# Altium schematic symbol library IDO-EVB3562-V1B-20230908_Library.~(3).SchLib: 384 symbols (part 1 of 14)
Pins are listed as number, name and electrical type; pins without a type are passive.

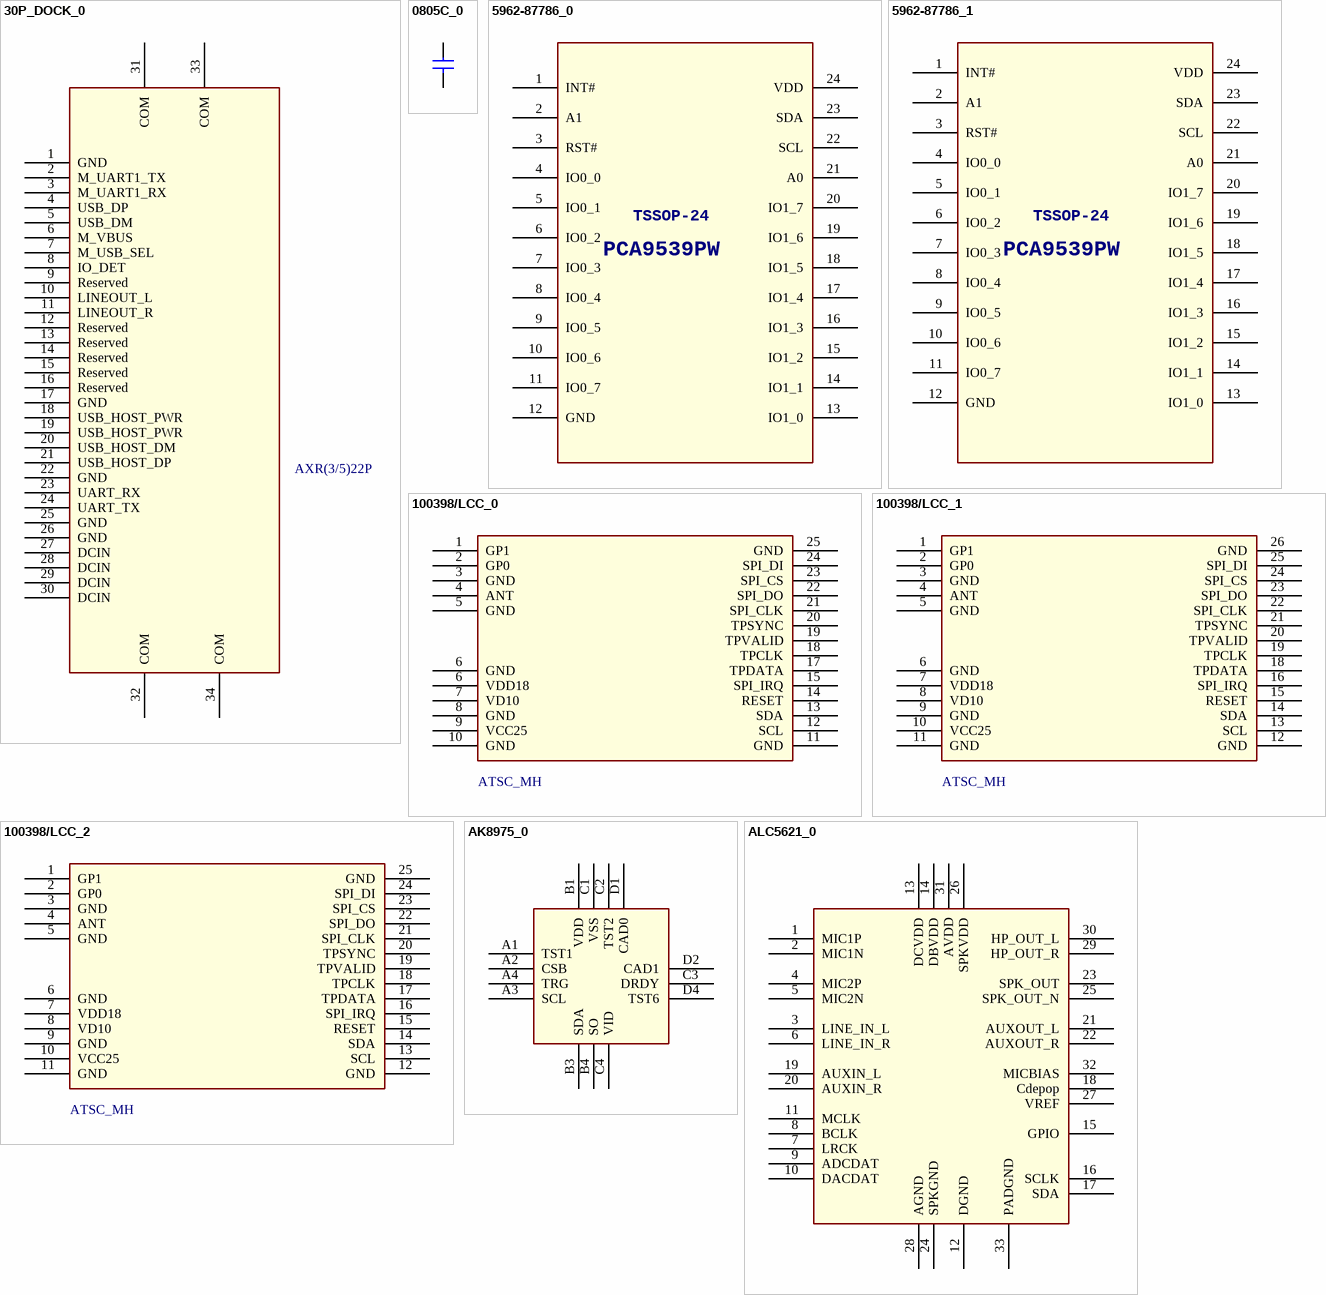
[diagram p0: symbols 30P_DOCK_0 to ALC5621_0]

## 30P_DOCK_0
designator CON?, comment AXR(3/5)22P
Altium-Right: 140; Altium-Bottom: 390
footprint 30P_DOCK_1
pins: 1 GND, 2 M_UART1_TX, 3 M_UART1_RX, 4 USB_DP, 5 USB_DM, 6 M_VBUS, 7 M_USB_SEL, 8 IO_DET, 9 Reserved, 10 LINEOUT_L, 11 LINEOUT_R, 12 Reserved, 13 Reserved, 14 Reserved, 15 Reserved, 16 Reserved, 17 GND, 18 USB_HOST_PWR, 19 USB_HOST_PWR, 20 USB_HOST_DM, 21 USB_HOST_DP, 22 GND, 23 UART_RX, 24 UART_TX, 25 GND, 26 GND, 27 DCIN, 28 DCIN, 29 DCIN, 30 DCIN, 31 COM, 32 COM, 33 COM, 34 COM

## 0805C_0
designator C?
Altium-Right: 20; Altium-Bottom: 10
footprint 0805C
pins: 1, 2

## 5962-87786_0
designator U?
Altium-Right: 170; Altium-Bottom: 280
pins: 1 INT#, 2 A1, 3 RST#, 4 IO0_0, 5 IO0_1, 6 IO0_2, 7 IO0_3, 8 IO0_4, 9 IO0_5, 10 IO0_6, 11 IO0_7, 12 GND, 13 IO1_0, 14 IO1_1, 15 IO1_2, 16 IO1_3, 17 IO1_4, 18 IO1_5, 19 IO1_6, 20 IO1_7, 21 A0, 22 SCL, 23 SDA, 24 VDD

## 5962-87786_1
designator U?
Altium-Right: 170; Altium-Bottom: 280
pins: 1 INT#, 2 A1, 3 RST#, 4 IO0_0, 5 IO0_1, 6 IO0_2, 7 IO0_3, 8 IO0_4, 9 IO0_5, 10 IO0_6, 11 IO0_7, 12 GND, 13 IO1_0, 14 IO1_1, 15 IO1_2, 16 IO1_3, 17 IO1_4, 18 IO1_5, 19 IO1_6, 20 IO1_7, 21 A0, 22 SCL, 23 SDA, 24 VDD

## 100398/LCC_0
designator U?, comment ATSC_MH
Altium-Right: 210; Altium-Bottom: 150
pins: 1 GP1, 2 GP0, 3 GND, 4 ANT, 5 GND, 6 VDD18, 6 GND, 7 VD10, 8 GND, 9 VCC25, 10 GND, 11 GND, 12 SCL, 13 SDA, 14 RESET, 15 SPI_IRQ, 17 TPDATA, 18 TPCLK, 19 TPVALID, 20 TPSYNC, 21 SPI_CLK, 22 SPI_DO, 23 SPI_CS, 24 SPI_DI, 25 GND

## 100398/LCC_1
designator U?, comment ATSC_MH
Altium-Right: 210; Altium-Bottom: 150
pins: 1 GP1, 2 GP0, 3 GND, 4 ANT, 5 GND, 6 GND, 7 VDD18, 8 VD10, 9 GND, 10 VCC25, 11 GND, 12 GND, 13 SCL, 14 SDA, 15 RESET, 16 SPI_IRQ, 18 TPDATA, 19 TPCLK, 20 TPVALID, 21 TPSYNC, 22 SPI_CLK, 23 SPI_DO, 24 SPI_CS, 25 SPI_DI, 26 GND

## 100398/LCC_2
designator U?, comment ATSC_MH
Altium-Right: 210; Altium-Bottom: 150
pins: 1 GP1, 2 GP0, 3 GND, 4 ANT, 5 GND, 6 GND, 7 VDD18, 8 VD10, 9 GND, 10 VCC25, 11 GND, 12 GND, 13 SCL, 14 SDA, 15 RESET, 16 SPI_IRQ, 17 TPDATA, 18 TPCLK, 19 TPVALID, 20 TPSYNC, 21 SPI_CLK, 22 SPI_DO, 23 SPI_CS, 24 SPI_DI, 25 GND

## AK8975_0
designator U?
Altium-Right: 90
footprint QFN16-4X4
pins: A1 TST1, A2 CSB, A3 SCL, A4 TRG, B1 VDD, B3 SDA, B4 SO, C1 VSS, C2 TST2, C3 DRDY, C4 VID, D1 CAD0, D2 CAD1, D4 TST6

## ALC5621_0
designator U?
Altium-Right: 170; Altium-Bottom: 210
footprint QFN32
pins: 1 MIC1P, 2 MIC1N, 3 LINE_IN_L, 4 MIC2P, 5 MIC2N, 6 LINE_IN_R, 7 LRCK, 8 BCLK, 9 ADCDAT, 10 DACDAT, 11 MCLK, 12 DGND, 13 DCVDD, 14 DBVDD, 15 GPIO, 16 SCLK, 17 SDA, 18 Cdepop, 19 AUXIN_L, 20 AUXIN_R, 21 AUXOUT_L, 22 AUXOUT_R, 23 SPK_OUT, 24 SPKGND, 25 SPK_OUT_N, 26 SPKVDD, 27 VREF, 28 AGND, 29 HP_OUT_R, 30 HP_OUT_L, 31 AVDD, 32 MICBIAS, 33 PADGND

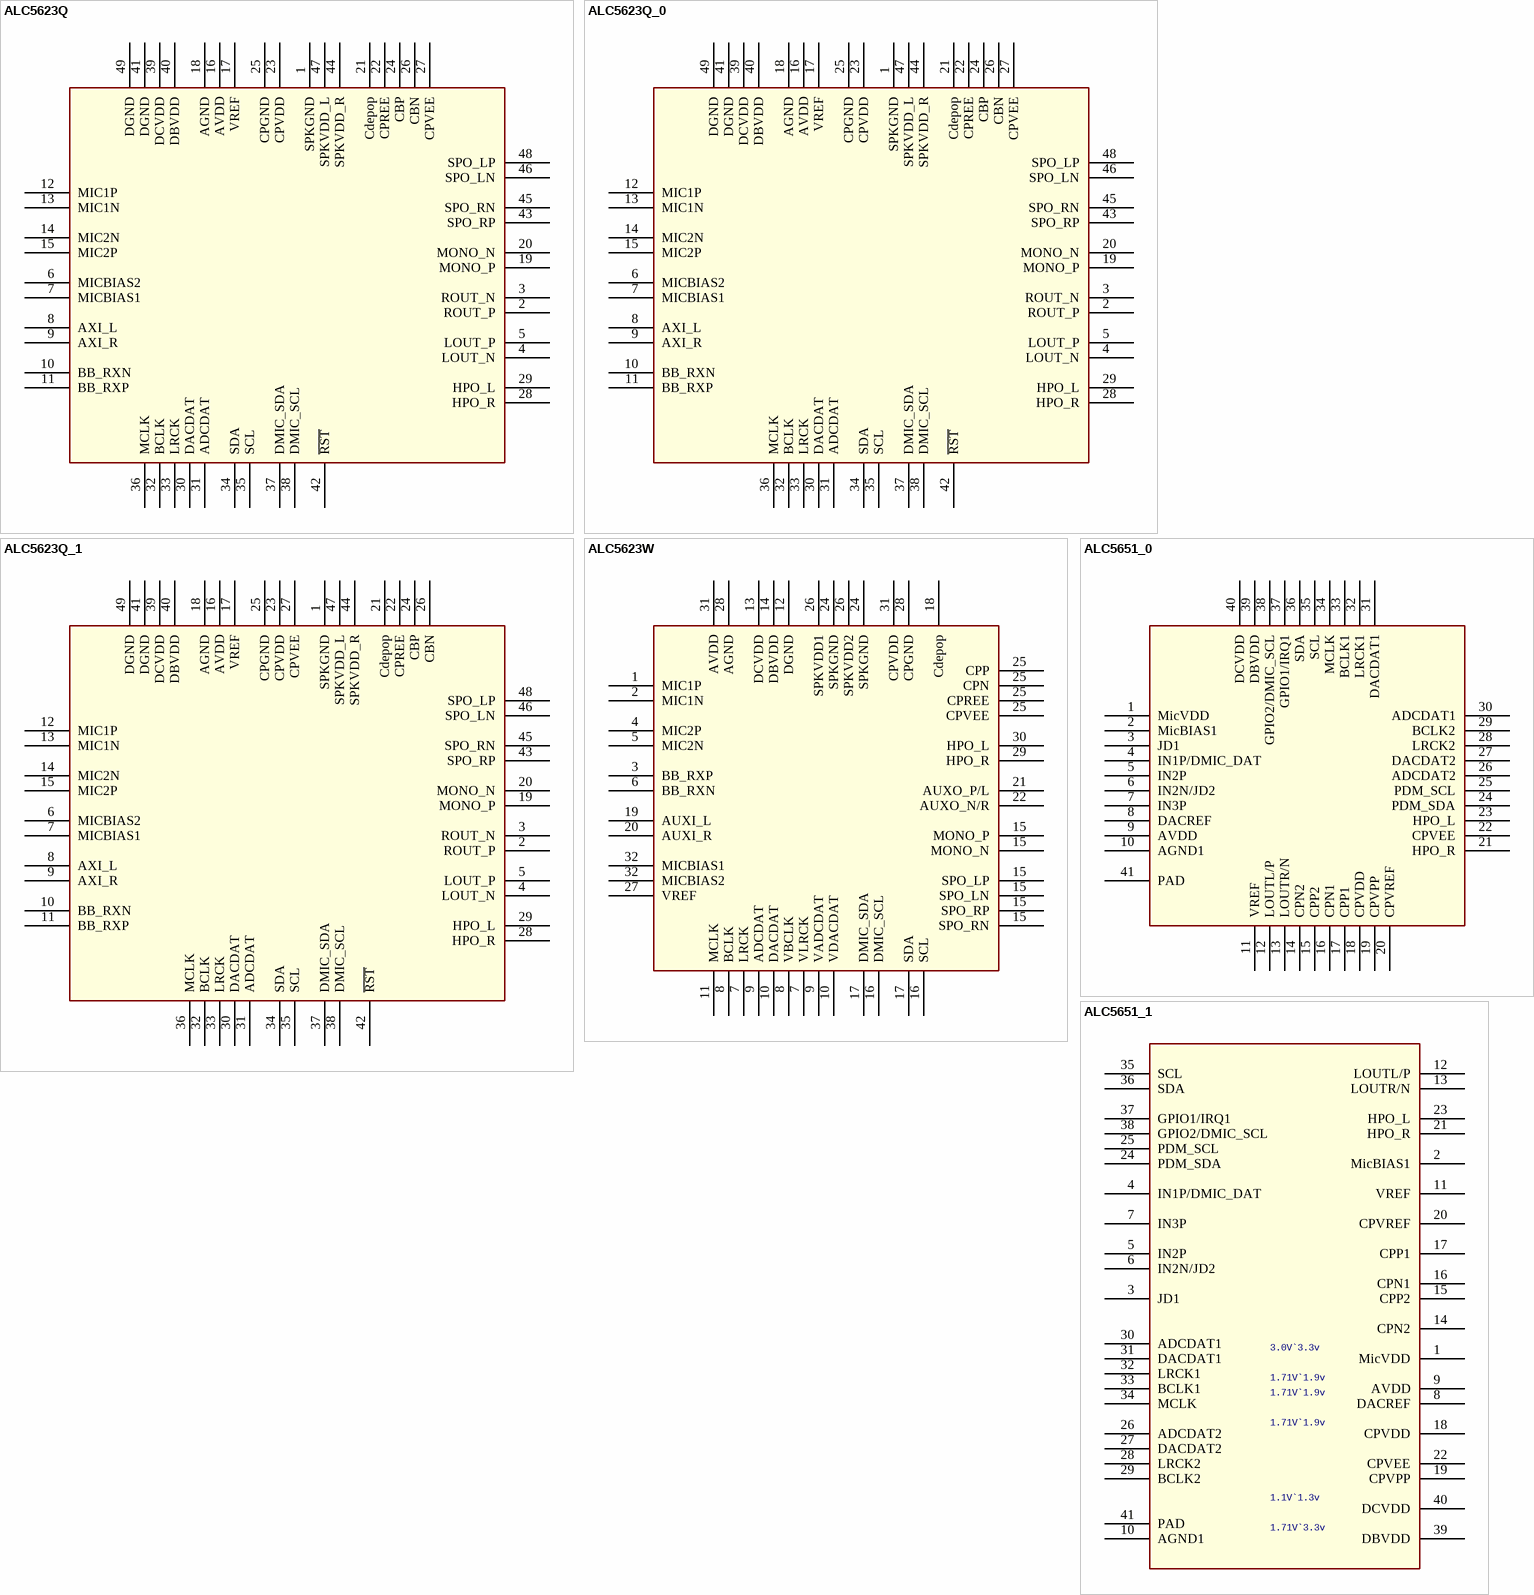
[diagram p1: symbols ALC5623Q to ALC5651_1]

## ALC5623Q
designator U?
Altium-Right: 290; Altium-Bottom: 250
footprint QFN48-6X6
pins: 1 SPKGND, 2 ROUT_P, 3 ROUT_N, 4 LOUT_N, 5 LOUT_P, 6 MICBIAS2, 7 MICBIAS1, 8 AXI_L, 9 AXI_R, 10 BB_RXN, 11 BB_RXP, 12 MIC1P, 13 MIC1N, 14 MIC2N, 15 MIC2P, 16 AVDD, 17 VREF, 18 AGND, 19 MONO_P, 20 MONO_N, 21 Cdepop, 22 CPREE, 23 CPVDD, 24 CBP, 25 CPGND, 26 CBN, 27 CPVEE, 28 HPO_R, 29 HPO_L, 30 DACDAT, 31 ADCDAT, 32 BCLK, 33 LRCK, 34 SDA, 35 SCL, 36 MCLK, 37 DMIC_SDA, 38 DMIC_SCL, 39 DCVDD, 40 DBVDD, 41 DGND, 42 ~{RST}, 43 SPO_RP, 44 SPKVDD_R, 45 SPO_RN, 46 SPO_LN, 47 SPKVDD_L, 48 SPO_LP, 49 DGND

## ALC5623Q_0
designator U?
Altium-Right: 290; Altium-Bottom: 250
footprint QFN48-6X6
pins: 1 SPKGND, 2 ROUT_P, 3 ROUT_N, 4 LOUT_N, 5 LOUT_P, 6 MICBIAS2, 7 MICBIAS1, 8 AXI_L, 9 AXI_R, 10 BB_RXN, 11 BB_RXP, 12 MIC1P, 13 MIC1N, 14 MIC2N, 15 MIC2P, 16 AVDD, 17 VREF, 18 AGND, 19 MONO_P, 20 MONO_N, 21 Cdepop, 22 CPREE, 23 CPVDD, 24 CBP, 25 CPGND, 26 CBN, 27 CPVEE, 28 HPO_R, 29 HPO_L, 30 DACDAT, 31 ADCDAT, 32 BCLK, 33 LRCK, 34 SDA, 35 SCL, 36 MCLK, 37 DMIC_SDA, 38 DMIC_SCL, 39 DCVDD, 40 DBVDD, 41 DGND, 42 ~{RST}, 43 SPO_RP, 44 SPKVDD_R, 45 SPO_RN, 46 SPO_LN, 47 SPKVDD_L, 48 SPO_LP, 49 DGND

## ALC5623Q_1
designator U?
Altium-Right: 290; Altium-Bottom: 250
footprint QFN48-6X6
pins: 1 SPKGND, 2 ROUT_P, 3 ROUT_N, 4 LOUT_N, 5 LOUT_P, 6 MICBIAS2, 7 MICBIAS1, 8 AXI_L, 9 AXI_R, 10 BB_RXN, 11 BB_RXP, 12 MIC1P, 13 MIC1N, 14 MIC2N, 15 MIC2P, 16 AVDD, 17 VREF, 18 AGND, 19 MONO_P, 20 MONO_N, 21 Cdepop, 22 CPREE, 23 CPVDD, 24 CBP, 25 CPGND, 26 CBN, 27 CPVEE, 28 HPO_R, 29 HPO_L, 30 DACDAT, 31 ADCDAT, 32 BCLK, 33 LRCK, 34 SDA, 35 SCL, 36 MCLK, 37 DMIC_SDA, 38 DMIC_SCL, 39 DCVDD, 40 DBVDD, 41 DGND, 42 ~{RST}, 43 SPO_RP, 44 SPKVDD_R, 45 SPO_RN, 46 SPO_LN, 47 SPKVDD_L, 48 SPO_LP, 49 DGND

## ALC5623W
designator U?
Altium-Right: 230
footprint GBA49
pins: 1 MIC1P, 2 MIC1N, 3 BB_RXP, 4 MIC2P, 5 MIC2N, 6 BB_RXN, 7 LRCK, 7 VLRCK, 8 BCLK, 8 VBCLK, 9 ADCDAT, 9 VADCDAT, 10 DACDAT, 10 VDACDAT, 11 MCLK, 12 DGND, 13 DCVDD, 14 DBVDD, 15 SPO_RN, 15 SPO_RP, 15 SPO_LP, 15 SPO_LN, 15 MONO_P, 15 MONO_N, 16 SCL, 16 DMIC_SCL, 17 SDA, 17 DMIC_SDA, 18 Cdepop, 19 AUXI_L, 20 AUXI_R, 21 AUXO_P/L, 22 AUXO_N/R, 24 SPKGND, 24 SPKGND, 25 CPVEE, 25 CPREE, 25 CPN, 25 CPP, 26 SPKVDD1, 26 SPKVDD2, 27 VREF, 28 AGND, 28 CPGND, 29 HPO_R, 30 HPO_L, 31 AVDD, 31 CPVDD, 32 MICBIAS1, 32 MICBIAS2

## ALC5651_0
designator U?
Altium-Right: 210; Altium-Bottom: 200
footprint QFN-5RX5RX1R
pins: 1 MicVDD, 2 MicBIAS1, 3 JD1, 4 IN1P/DMIC_DAT, 5 IN2P, 6 IN2N/JD2, 7 IN3P, 8 DACREF, 9 AVDD, 10 AGND1, 11 VREF, 12 LOUTL/P, 13 LOUTR/N, 14 CPN2, 15 CPP2, 16 CPN1, 17 CPP1, 18 CPVDD, 19 CPVPP, 20 CPVREF, 21 HPO_R, 22 CPVEE, 23 HPO_L, 24 PDM_SDA, 25 PDM_SCL, 26 ADCDAT2, 27 DACDAT2, 28 LRCK2, 29 BCLK2, 30 ADCDAT1, 31 DACDAT1, 32 LRCK1, 33 BCLK1, 34 MCLK, 35 SCL, 36 SDA, 37 GPIO1/IRQ1, 38 GPIO2/DMIC_SCL, 39 DBVDD, 40 DCVDD, 41 PAD

## ALC5651_1
designator U?
Altium-Right: 180; Altium-Bottom: 350
footprint QFN-5RX5RX1R
pins: 1 MicVDD, 2 MicBIAS1, 3 JD1, 4 IN1P/DMIC_DAT, 5 IN2P, 6 IN2N/JD2, 7 IN3P, 8 DACREF, 9 AVDD, 10 AGND1, 11 VREF, 12 LOUTL/P, 13 LOUTR/N, 14 CPN2, 15 CPP2, 16 CPN1, 17 CPP1, 18 CPVDD, 19 CPVPP, 20 CPVREF, 21 HPO_R, 22 CPVEE, 23 HPO_L, 24 PDM_SDA, 25 PDM_SCL, 26 ADCDAT2, 27 DACDAT2, 28 LRCK2, 29 BCLK2, 30 ADCDAT1, 31 DACDAT1, 32 LRCK1, 33 BCLK1, 34 MCLK, 35 SCL, 36 SDA, 37 GPIO1/IRQ1, 38 GPIO2/DMIC_SCL, 39 DBVDD, 40 DCVDD, 41 PAD

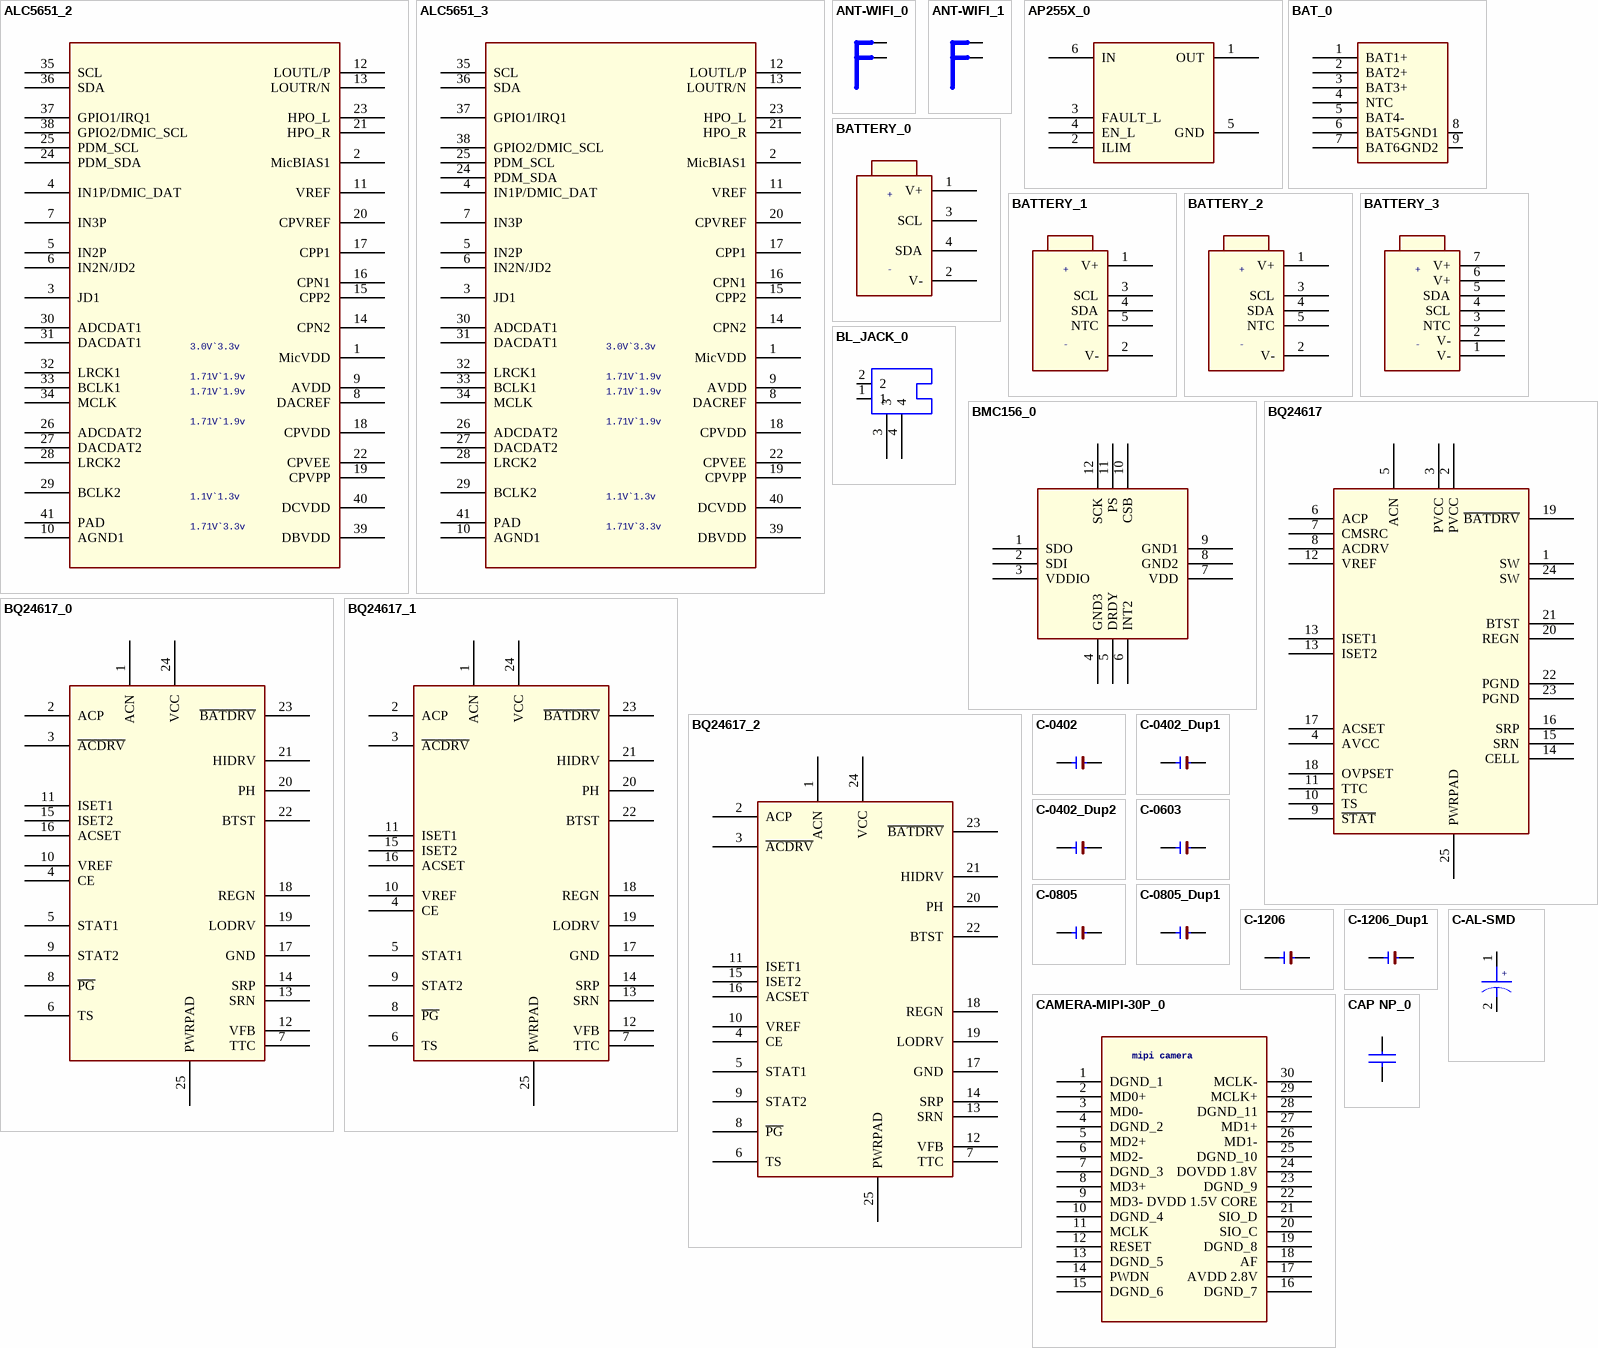
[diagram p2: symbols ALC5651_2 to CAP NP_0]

## ALC5651_2
designator U?
Altium-Right: 180; Altium-Bottom: 350
footprint QFN-5RX5RX1R
pins: 1 MicVDD, 2 MicBIAS1, 3 JD1, 4 IN1P/DMIC_DAT, 5 IN2P, 6 IN2N/JD2, 7 IN3P, 8 DACREF, 9 AVDD, 10 AGND1, 11 VREF, 12 LOUTL/P, 13 LOUTR/N, 14 CPN2, 15 CPP2, 16 CPN1, 17 CPP1, 18 CPVDD, 19 CPVPP, 20 CPVREF, 21 HPO_R, 22 CPVEE, 23 HPO_L, 24 PDM_SDA, 25 PDM_SCL, 26 ADCDAT2, 27 DACDAT2, 28 LRCK2, 29 BCLK2, 30 ADCDAT1, 31 DACDAT1, 32 LRCK1, 33 BCLK1, 34 MCLK, 35 SCL, 36 SDA, 37 GPIO1/IRQ1, 38 GPIO2/DMIC_SCL, 39 DBVDD, 40 DCVDD, 41 PAD

## ALC5651_3
designator U?
Altium-Right: 180; Altium-Bottom: 350
footprint QFN-5RX5RX1R
pins: 1 MicVDD, 2 MicBIAS1, 3 JD1, 4 IN1P/DMIC_DAT, 5 IN2P, 6 IN2N/JD2, 7 IN3P, 8 DACREF, 9 AVDD, 10 AGND1, 11 VREF, 12 LOUTL/P, 13 LOUTR/N, 14 CPN2, 15 CPP2, 16 CPN1, 17 CPP1, 18 CPVDD, 19 CPVPP, 20 CPVREF, 21 HPO_R, 22 CPVEE, 23 HPO_L, 24 PDM_SDA, 25 PDM_SCL, 26 ADCDAT2, 27 DACDAT2, 28 LRCK2, 29 BCLK2, 30 ADCDAT1, 31 DACDAT1, 32 LRCK1, 33 BCLK1, 34 MCLK, 35 SCL, 36 SDA, 37 GPIO1/IRQ1, 38 GPIO2/DMIC_SCL, 39 DBVDD, 40 DCVDD, 41 PAD

## ANT-WIFI_0
designator C?
Altium-Right: 20; Altium-Bottom: 32
pins: 1, 2

## ANT-WIFI_1
designator C?
Altium-Right: 20; Altium-Bottom: 32
pins: 1, 2

## AP255X_0
designator U?
Altium-Right: 80
pins: 1 OUT, 2 ILIM, 3 FAULT_L, 4 EN_L, 5 GND, 6 IN

## BAT_0
designator J?
Altium-Right: 60; Altium-Bottom: 80
footprint BATT_10PINS
pins: 1 BAT1+, 2 BAT2+, 3 BAT3+, 4 NTC, 5 BAT4-, 6 BAT5-, 7 BAT6-, 8 GND1, 9 GND2

## BATTERY_0
designator BT?
Altium-Right: 50; Altium-Bottom: 90
pins: 1 V+, 2 V-, 3 SCL, 4 SDA

## BATTERY_1
designator BT?
Altium-Right: 50; Altium-Bottom: 90
pins: 1 V+, 2 V-, 3 SCL, 4 SDA, 5 NTC

## BATTERY_2
designator BT?
Altium-Right: 50; Altium-Bottom: 90
pins: 1 V+, 2 V-, 3 SCL, 4 SDA, 5 NTC

## BATTERY_3
designator BT?
Altium-Right: 50; Altium-Bottom: 90
pins: 1 V-, 2 V-, 3 NTC, 4 SCL, 5 SDA, 6 V+, 7 V+

## BL_JACK_0
designator J?
Altium-Right: 40; Altium-Bottom: 30
pins: 1, 2, 3, 4

## BMC156_0
designator U?
Altium-Right: 100
pins: 1 SDO, 2 SDI, 3 VDDIO, 4 GND3, 5 DRDY, 6 INT2, 7 VDD, 8 GND2, 9 GND1, 10 CSB, 11 PS, 12 SCK

## BQ24617
designator U?
Altium-Right: 130; Altium-Bottom: 230
footprint QFN24
pins: 1 SW, 2 PVCC, 3 PVCC, 4 AVCC, 5 ACN, 6 ACP, 7 CMSRC, 8 ACDRV, 9 ~{STAT}, 10 TS, 11 TTC, 12 VREF, 13 ISET1, 13 ISET2, 14 CELL, 15 SRN, 16 SRP, 17 ACSET, 18 OVPSET, 19 ~{BATDRV}, 20 REGN, 21 BTST, 22 PGND, 23 PGND, 24 SW, 25 PWRPAD

## BQ24617_0
designator U?
Altium-Right: 130; Altium-Bottom: 250
footprint QFN24
pins: 1 ACN, 2 ACP, 3 ~{ACDRV}, 4 CE, 5 STAT1, 6 TS, 7 TTC, 8 ~{PG}, 9 STAT2, 10 VREF, 11 ISET1, 12 VFB, 13 SRN, 14 SRP, 15 ISET2, 16 ACSET, 17 GND, 18 REGN, 19 LODRV, 20 PH, 21 HIDRV, 22 BTST, 23 ~{BATDRV}, 24 VCC, 25 PWRPAD

## BQ24617_1
designator U?
Altium-Right: 130; Altium-Bottom: 250
footprint QFN24
pins: 1 ACN, 2 ACP, 3 ~{ACDRV}, 4 CE, 5 STAT1, 6 TS, 7 TTC, 8 ~{PG}, 9 STAT2, 10 VREF, 11 ISET1, 12 VFB, 13 SRN, 14 SRP, 15 ISET2, 16 ACSET, 17 GND, 18 REGN, 19 LODRV, 20 PH, 21 HIDRV, 22 BTST, 23 ~{BATDRV}, 24 VCC, 25 PWRPAD

## BQ24617_2
designator U?
Altium-Right: 130; Altium-Bottom: 250
footprint QFN24
pins: 1 ACN, 2 ACP, 3 ~{ACDRV}, 4 CE, 5 STAT1, 6 TS, 7 TTC, 8 ~{PG}, 9 STAT2, 10 VREF, 11 ISET1, 12 VFB, 13 SRN, 14 SRP, 15 ISET2, 16 ACSET, 17 GND, 18 REGN, 19 LODRV, 20 PH, 21 HIDRV, 22 BTST, 23 ~{BATDRV}, 24 VCC, 25 PWRPAD

## C-0402
designator C?
Altium-Right: 10; Altium-Bottom: 20
footprint 1206
pins: 1, 2

## C-0402_Dup1
designator C?
Altium-Right: 10; Altium-Bottom: 20
footprint 1206
pins: 1, 2

## C-0402_Dup2
designator C?
Altium-Right: 10; Altium-Bottom: 20
footprint 1206
pins: 1, 2

## C-0603
designator C?
Altium-Right: 10; Altium-Bottom: 20
footprint 1206
pins: 1, 2

## C-0805
designator C?
Altium-Right: 10; Altium-Bottom: 20
footprint 1206
pins: 1, 2

## C-0805_Dup1
designator C?
Altium-Right: 10; Altium-Bottom: 20
footprint 1206
pins: 1, 2

## C-1206
designator C?
Altium-Right: 10; Altium-Bottom: 20
footprint 1206
pins: 1, 2

## C-1206_Dup1
designator C?
Altium-Right: 10; Altium-Bottom: 20
footprint 1206
pins: 1, 2

## C-AL-SMD
designator CP?
Altium-Right: 20
pins: 1, 2

## CAMERA-MIPI-30P_0
designator U?
Altium-Right: 110; Altium-Bottom: 190
pins: 1 DGND_1, 2 MD0+, 3 MD0-, 4 DGND_2, 5 MD2+, 6 MD2-, 7 DGND_3, 8 MD3+, 9 MD3-, 10 DGND_4, 11 MCLK, 12 RESET, 13 DGND_5, 14 PWDN, 15 DGND_6, 16 DGND_7, 17 AVDD 2.8V, 18 AF, 19 DGND_8, 20 SIO_C, 21 SIO_D, 22 DVDD 1.5V CORE, 23 DGND_9, 24 DOVDD 1.8V, 25 DGND_10, 26 MD1-, 27 MD1+, 28 DGND_11, 29 MCLK+, 30 MCLK-

## CAP NP_0
designator C?
Altium-Right: 20; Altium-Bottom: 10
pins: 1, 2

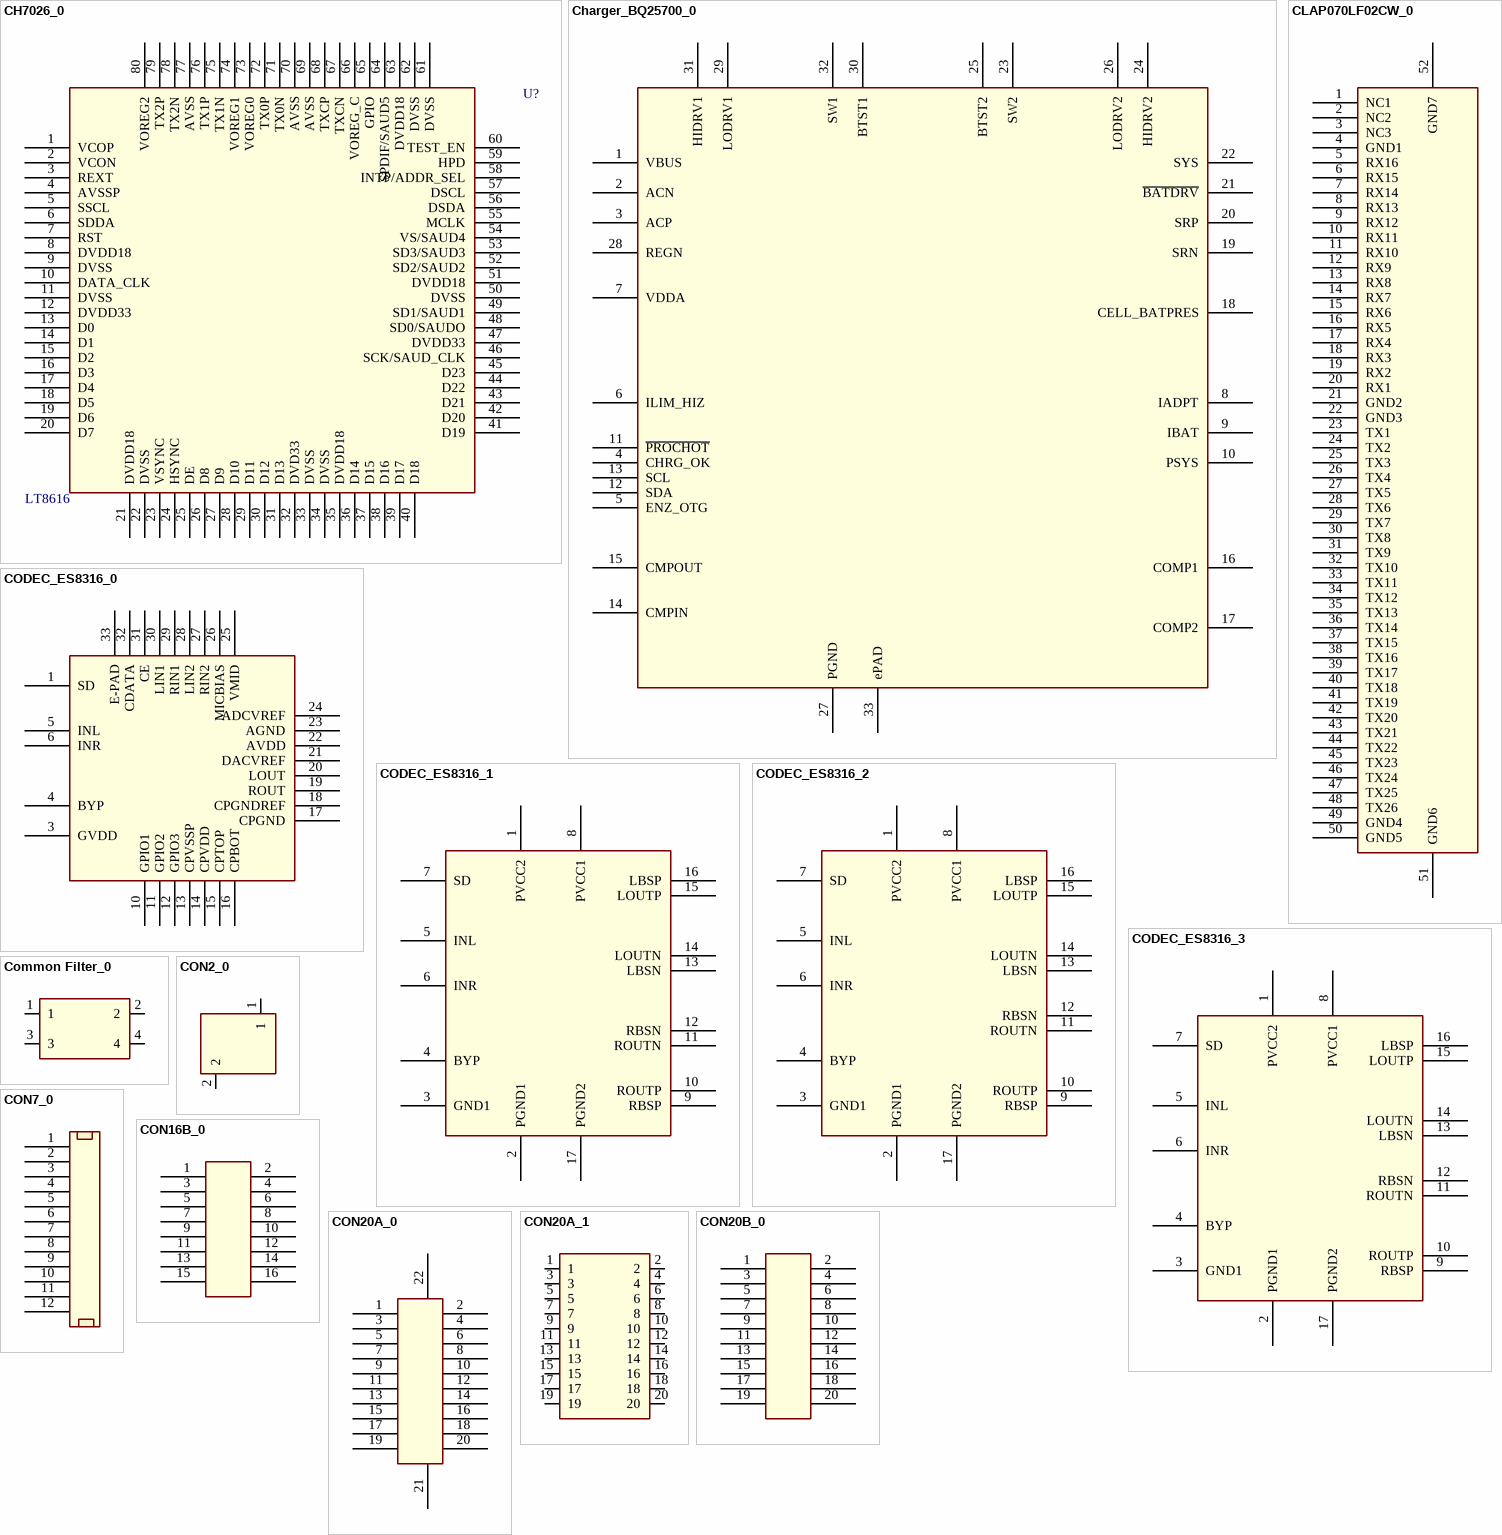
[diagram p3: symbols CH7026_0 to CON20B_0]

## CH7026_0
designator U?, comment LT8616
Altium-Right: 270
footprint LQFP80
pins: 1 VCOP, 2 VCON, 3 REXT, 4 AVSSP, 5 SSCL, 6 SDDA, 7 RST, 8 DVDD18 (power), 9 DVSS (power), 10 DATA_CLK, 11 DVSS (power), 12 DVDD33 (power), 13 D0, 14 D1, 15 D2, 16 D3, 17 D4, 18 D5, 19 D6, 20 D7, 21 DVDD18 (power), 22 DVSS (power), 23 VSYNC, 24 HSYNC, 25 DE, 26 D8, 27 D9, 28 D10, 29 D11, 30 D12, 31 D13, 32 DVD33 (power), 33 DVSS (power), 34 DVSS (power), 35 DVDD18 (power), 36 D14, 37 D15, 38 D16, 39 D17, 40 D18, 41 D19, 42 D20, 43 D21, 44 D22, 45 D23, 46 SCK/SAUD_CLK, 47 DVDD33 (power), 48 SD0/SAUDO, 49 SD1/SAUD1, 50 DVSS (power), 51 DVDD18 (power), 52 SD2/SAUD2, 53 SD3/SAUD3, 54 VS/SAUD4, 55 MCLK, 56 DSDA, 57 DSCL, 58 INTP/ADDR_SEL, 59 HPD, 60 TEST_EN, 61 DVSS (power), 62 DVSS (power), 63 DVDD18 (power), 64 SPDIF/SAUD5, 65 GPIO, 66 VOREG_C, 67 TXCN, 68 TXCP, 69 AVSS (power), 70 AVSS (power), 71 TX0N, 72 TX0P, 73 VOREG0, 74 VOREG1, 75 TX1N, 76 TX1P, 77 AVSS (power), 78 TX2N, 79 TX2P, 80 VOREG2

## Charger_BQ25700_0
designator U?
Altium-Right: 380; Altium-Bottom: 400
footprint TBD
pins: 1 VBUS, 2 ACN, 3 ACP, 4 CHRG_OK, 5 ENZ_OTG, 6 ILIM_HIZ, 7 VDDA, 8 IADPT, 9 IBAT, 10 PSYS, 11 ~{PROCHOT}, 12 SDA, 13 SCL, 14 CMPIN, 15 CMPOUT, 16 COMP1, 17 COMP2, 18 CELL_BATPRES, 19 SRN, 20 SRP, 21 ~{BATDRV}, 22 SYS, 23 SW2, 24 HIDRV2, 25 BTST2, 26 LODRV2, 27 PGND, 28 REGN, 29 LODRV1, 30 BTST1, 31 HIDRV1, 32 SW1, 33 ePAD

## CLAP070LF02CW_0
designator U?
Altium-Right: 80; Altium-Bottom: 510
pins: 1 NC1, 2 NC2, 3 NC3, 4 GND1, 5 RX16, 6 RX15, 7 RX14, 8 RX13, 9 RX12, 10 RX11, 11 RX10, 12 RX9, 13 RX8, 14 RX7, 15 RX6, 16 RX5, 17 RX4, 18 RX3, 19 RX2, 20 RX1, 21 GND2, 22 GND3, 23 TX1, 24 TX2, 25 TX3, 26 TX4, 27 TX5, 28 TX6, 29 TX7, 30 TX8, 31 TX9, 32 TX10, 33 TX11, 34 TX12, 35 TX13, 36 TX14, 37 TX15, 38 TX16, 39 TX17, 40 TX18, 41 TX19, 42 TX20, 43 TX21, 44 TX22, 45 TX23, 46 TX24, 47 TX25, 48 TX26, 49 GND4, 50 GND5, 51 GND6, 52 GND7

## CODEC_ES8316_0
designator U?
Altium-Right: 150
pins: 1 SD, 3 GVDD, 4 BYP, 5 INL, 6 INR, 10 GPIO1, 11 GPIO2, 12 GPIO3, 13 CPVSSP, 14 CPVDD, 15 CPTOP, 16 CPBOT, 17 CPGND, 18 CPGNDREF, 19 ROUT, 20 LOUT, 21 DACVREF, 22 AVDD, 23 AGND, 24 ADCVREF, 25 VMID, 26 MICBIAS, 27 RIN2, 28 LIN2, 29 RIN1, 30 LIN1, 31 CE, 32 CDATA, 33 E-PAD

## CODEC_ES8316_1
designator U?
Altium-Right: 150; Altium-Bottom: 190
pins: 1 PVCC2, 2 PGND1, 3 GND1, 4 BYP, 5 INL, 6 INR, 7 SD, 8 PVCC1, 9 RBSP, 10 ROUTP, 11 ROUTN, 12 RBSN, 13 LBSN, 14 LOUTN, 15 LOUTP, 16 LBSP, 17 PGND2

## CODEC_ES8316_2
designator U?
Altium-Right: 150; Altium-Bottom: 190
pins: 1 PVCC2, 2 PGND1, 3 GND1, 4 BYP, 5 INL, 6 INR, 7 SD, 8 PVCC1, 9 RBSP, 10 ROUTP, 11 ROUTN, 12 RBSN, 13 LBSN, 14 LOUTN, 15 LOUTP, 16 LBSP, 17 PGND2

## CODEC_ES8316_3
designator U?
Altium-Right: 150; Altium-Bottom: 190
pins: 1 PVCC2, 2 PGND1, 3 GND1, 4 BYP, 5 INL, 6 INR, 7 SD, 8 PVCC1, 9 RBSP, 10 ROUTP, 11 ROUTN, 12 RBSN, 13 LBSN, 14 LOUTN, 15 LOUTP, 16 LBSP, 17 PGND2

## Common Filter_0
designator L?
Altium-Right: 60; Altium-Bottom: 40
pins: 1, 2, 3, 4

## CON2_0
designator J?
Altium-Right: 50; Altium-Bottom: 40
pins: 1, 2

## CON7_0
designator J?
Altium-Right: 20; Altium-Bottom: 130
pins: 1, 2, 3, 4, 5, 6, 7, 8, 9, 10, 11, 12

## CON16B_0
designator J?
Altium-Right: 30; Altium-Bottom: 90
pins: 1, 2, 3, 4, 5, 6, 7, 8, 9, 10, 11, 12, 13, 14, 15, 16

## CON20A_0
designator J?
Altium-Right: 30; Altium-Bottom: 110
pins: 1, 2, 3, 4, 5, 6, 7, 8, 9, 10, 11, 12, 13, 14, 15, 16, 17, 18, 19, 20, 21, 22

## CON20A_1
designator J?
Altium-Right: 60; Altium-Bottom: 110
pins: 1, 2, 3, 4, 5, 6, 7, 8, 9, 10, 11, 12, 13, 14, 15, 16, 17, 18, 19, 20

## CON20B_0
designator J?
Altium-Right: 30; Altium-Bottom: 110
pins: 1, 2, 3, 4, 5, 6, 7, 8, 9, 10, 11, 12, 13, 14, 15, 16, 17, 18, 19, 20

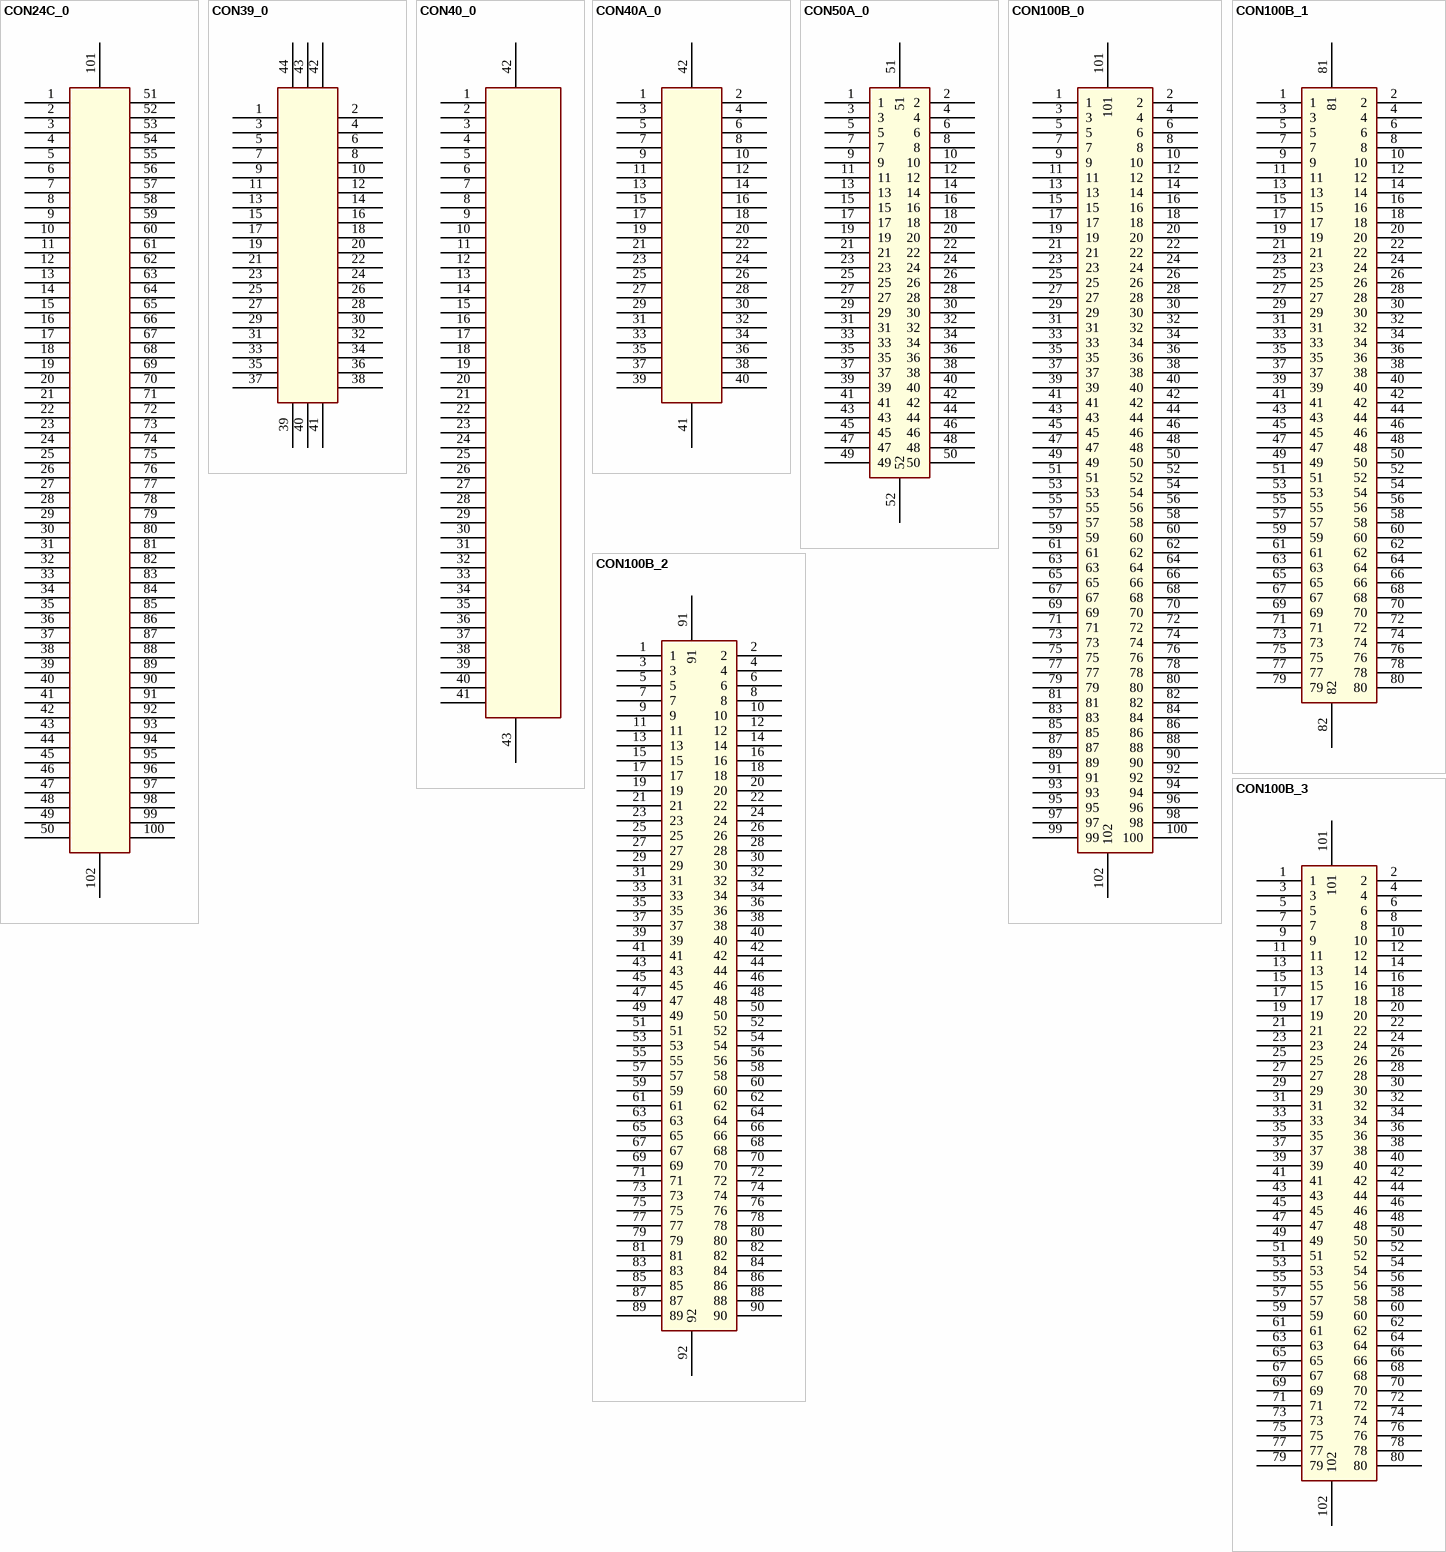
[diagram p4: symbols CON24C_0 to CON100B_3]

## CON24C_0
designator J?
Altium-Right: 40; Altium-Bottom: 510
pins: 1, 2, 3, 4, 5, 6, 7, 8, 9, 10, 11, 12, 13, 14, 15, 16, 17, 18, 19, 20, 21, 22, 23, 24, 25, 26, 27, 28, 29, 30, 31, 32, 33, 34, 35, 36, 37, 38, 39, 40, 41, 42, 43, 44, 45, 46, 47, 48, 49, 50, 51, 52, 53, 54, 55, 56, 57, 58, 59, 60, 61, 62, 63, 64, 65, 66, 67, 68, 69, 70, 71, 72, 73, 74, 75, 76, 77, 78, 79, 80, 81, 82, 83, 84, 85, 86, 87, 88, 89, 90, 91, 92, 93, 94, 95, 96, 97, 98, 99, 100, 101, 102

## CON39_0
designator J?
Altium-Right: 40; Altium-Bottom: 210
pins: 1, 2, 3, 4, 5, 6, 7, 8, 9, 10, 11, 12, 13, 14, 15, 16, 17, 18, 19, 20, 21, 22, 23, 24, 25, 26, 27, 28, 29, 30, 31, 32, 33, 34, 35, 36, 37, 38, 39, 40, 41, 42, 43, 44

## CON40_0
designator J?
Altium-Right: 50; Altium-Bottom: 420
pins: 1, 2, 3, 4, 5, 6, 7, 8, 9, 10, 11, 12, 13, 14, 15, 16, 17, 18, 19, 20, 21, 22, 23, 24, 25, 26, 27, 28, 29, 30, 31, 32, 33, 34, 35, 36, 37, 38, 39, 40, 41, 42, 43

## CON40A_0
designator J?
Altium-Right: 40; Altium-Bottom: 210
pins: 1, 2, 3, 4, 5, 6, 7, 8, 9, 10, 11, 12, 13, 14, 15, 16, 17, 18, 19, 20, 21, 22, 23, 24, 25, 26, 27, 28, 29, 30, 31, 32, 33, 34, 35, 36, 37, 38, 39, 40, 41, 42

## CON50A_0
designator J?
Altium-Right: 40; Altium-Bottom: 260
footprint 25PIN-S2.54
pins: 1, 2, 3, 4, 5, 6, 7, 8, 9, 10, 11, 12, 13, 14, 15, 16, 17, 18, 19, 20, 21, 22, 23, 24, 25, 26, 27, 28, 29, 30, 31, 32, 33, 34, 35, 36, 37, 38, 39, 40, 41, 42, 43, 44, 45, 46, 47, 48, 49, 50, 51, 52

## CON100B_0
designator J?
Altium-Right: 50; Altium-Bottom: 510
footprint 50PIN-S1.27
pins: 1, 2, 3, 4, 5, 6, 7, 8, 9, 10, 11, 12, 13, 14, 15, 16, 17, 18, 19, 20, 21, 22, 23, 24, 25, 26, 27, 28, 29, 30, 31, 32, 33, 34, 35, 36, 37, 38, 39, 40, 41, 42, 43, 44, 45, 46, 47, 48, 49, 50, 51, 52, 53, 54, 55, 56, 57, 58, 59, 60, 61, 62, 63, 64, 65, 66, 67, 68, 69, 70, 71, 72, 73, 74, 75, 76, 77, 78, 79, 80, 81, 82, 83, 84, 85, 86, 87, 88, 89, 90, 91, 92, 93, 94, 95, 96, 97, 98, 99, 100, 101, 102

## CON100B_1
designator J?
Altium-Right: 50; Altium-Bottom: 410
footprint 50PIN-S1.27
pins: 1, 2, 3, 4, 5, 6, 7, 8, 9, 10, 11, 12, 13, 14, 15, 16, 17, 18, 19, 20, 21, 22, 23, 24, 25, 26, 27, 28, 29, 30, 31, 32, 33, 34, 35, 36, 37, 38, 39, 40, 41, 42, 43, 44, 45, 46, 47, 48, 49, 50, 51, 52, 53, 54, 55, 56, 57, 58, 59, 60, 61, 62, 63, 64, 65, 66, 67, 68, 69, 70, 71, 72, 73, 74, 75, 76, 77, 78, 79, 80, 81, 82

## CON100B_2
designator J?
Altium-Right: 50; Altium-Bottom: 460
footprint 50PIN-S1.27
pins: 1, 2, 3, 4, 5, 6, 7, 8, 9, 10, 11, 12, 13, 14, 15, 16, 17, 18, 19, 20, 21, 22, 23, 24, 25, 26, 27, 28, 29, 30, 31, 32, 33, 34, 35, 36, 37, 38, 39, 40, 41, 42, 43, 44, 45, 46, 47, 48, 49, 50, 51, 52, 53, 54, 55, 56, 57, 58, 59, 60, 61, 62, 63, 64, 65, 66, 67, 68, 69, 70, 71, 72, 73, 74, 75, 76, 77, 78, 79, 80, 81, 82, 83, 84, 85, 86, 87, 88, 89, 90, 91, 92

## CON100B_3
designator J?
Altium-Right: 50; Altium-Bottom: 410
footprint 50PIN-S1.27
pins: 1, 2, 3, 4, 5, 6, 7, 8, 9, 10, 11, 12, 13, 14, 15, 16, 17, 18, 19, 20, 21, 22, 23, 24, 25, 26, 27, 28, 29, 30, 31, 32, 33, 34, 35, 36, 37, 38, 39, 40, 41, 42, 43, 44, 45, 46, 47, 48, 49, 50, 51, 52, 53, 54, 55, 56, 57, 58, 59, 60, 61, 62, 63, 64, 65, 66, 67, 68, 69, 70, 71, 72, 73, 74, 75, 76, 77, 78, 79, 80, 101, 102

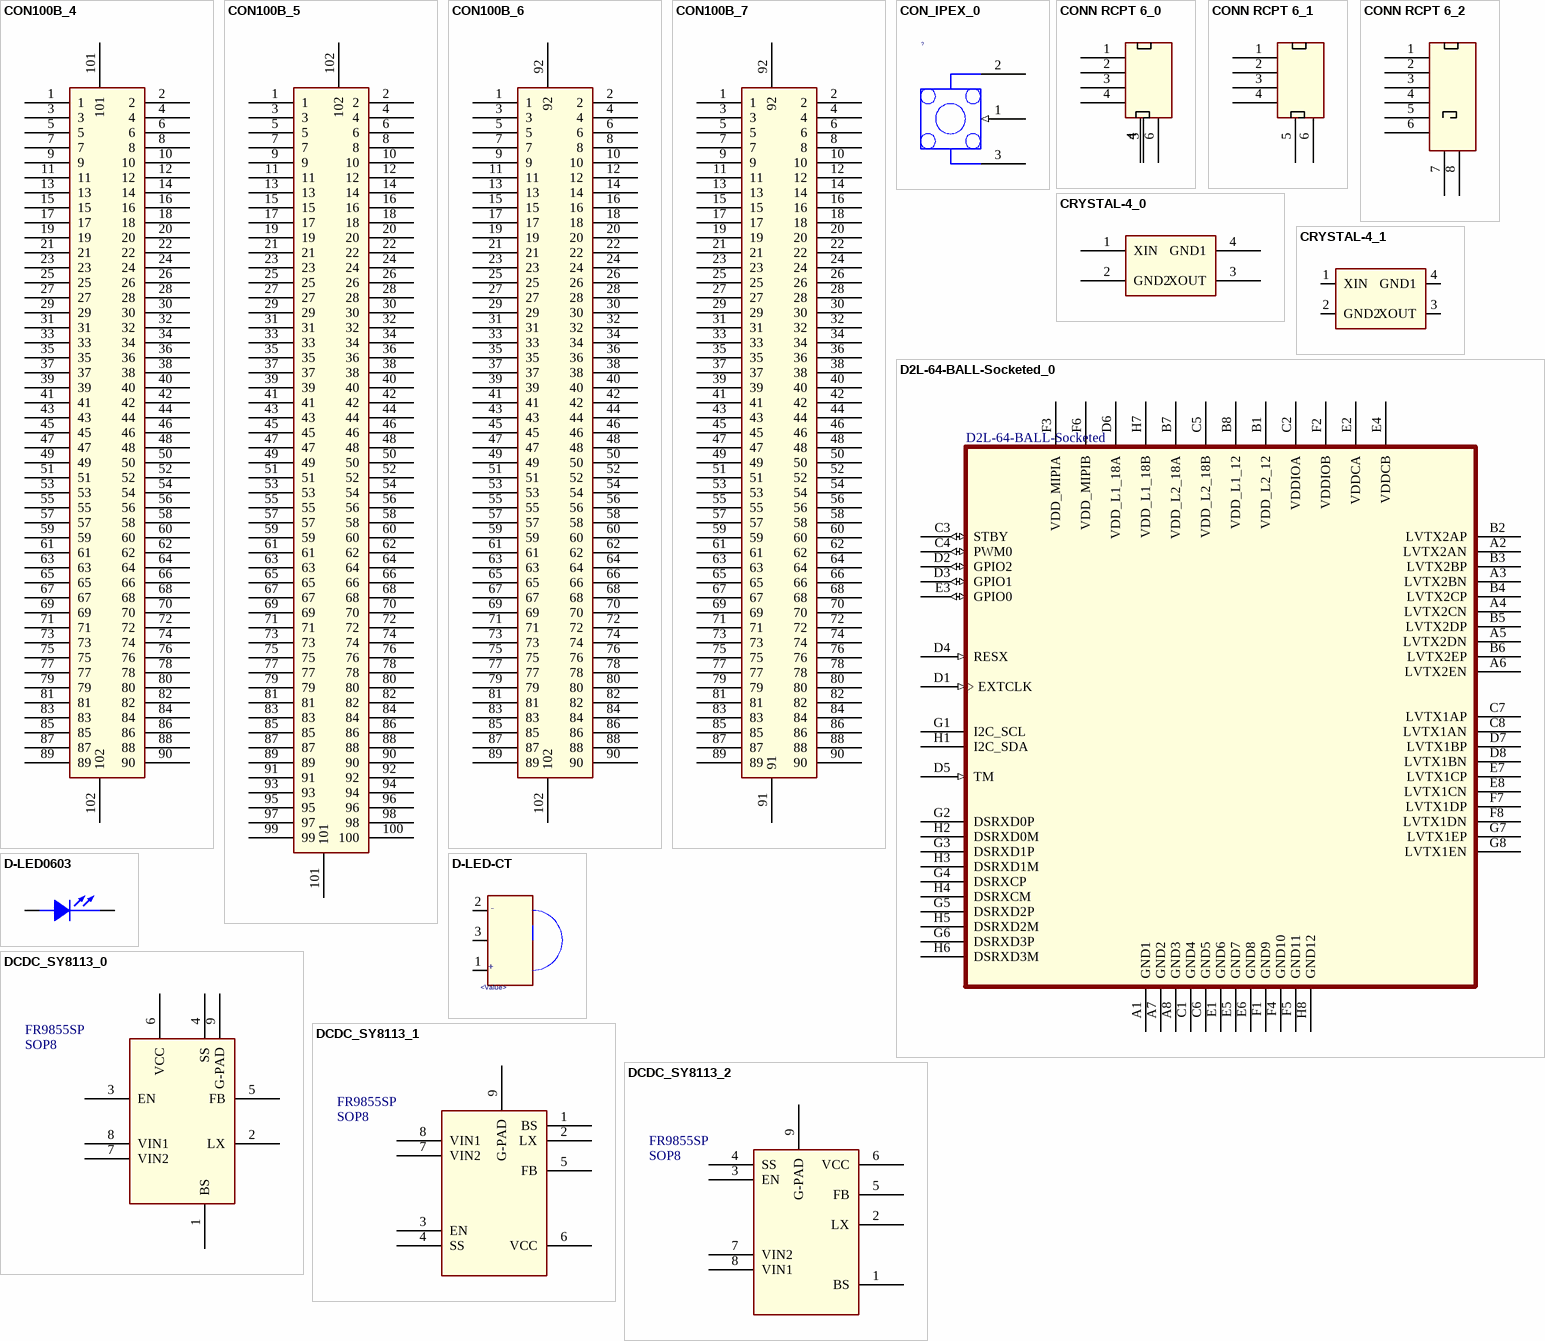
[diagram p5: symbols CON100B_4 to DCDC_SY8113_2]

## CON100B_4
designator J?
Altium-Right: 50; Altium-Bottom: 460
footprint 50PIN-S1.27
pins: 1, 2, 3, 4, 5, 6, 7, 8, 9, 10, 11, 12, 13, 14, 15, 16, 17, 18, 19, 20, 21, 22, 23, 24, 25, 26, 27, 28, 29, 30, 31, 32, 33, 34, 35, 36, 37, 38, 39, 40, 41, 42, 43, 44, 45, 46, 47, 48, 49, 50, 51, 52, 53, 54, 55, 56, 57, 58, 59, 60, 61, 62, 63, 64, 65, 66, 67, 68, 69, 70, 71, 72, 73, 74, 75, 76, 77, 78, 79, 80, 81, 82, 83, 84, 85, 86, 87, 88, 89, 90, 101, 102

## CON100B_5
designator J?
Altium-Right: 50; Altium-Bottom: 510
footprint 50PIN-S1.27
pins: 1, 2, 3, 4, 5, 6, 7, 8, 9, 10, 11, 12, 13, 14, 15, 16, 17, 18, 19, 20, 21, 22, 23, 24, 25, 26, 27, 28, 29, 30, 31, 32, 33, 34, 35, 36, 37, 38, 39, 40, 41, 42, 43, 44, 45, 46, 47, 48, 49, 50, 51, 52, 53, 54, 55, 56, 57, 58, 59, 60, 61, 62, 63, 64, 65, 66, 67, 68, 69, 70, 71, 72, 73, 74, 75, 76, 77, 78, 79, 80, 81, 82, 83, 84, 85, 86, 87, 88, 89, 90, 91, 92, 93, 94, 95, 96, 97, 98, 99, 100, 101, 102

## CON100B_6
designator J?
Altium-Right: 50; Altium-Bottom: 460
footprint 50PIN-S1.27
pins: 1, 2, 3, 4, 5, 6, 7, 8, 9, 10, 11, 12, 13, 14, 15, 16, 17, 18, 19, 20, 21, 22, 23, 24, 25, 26, 27, 28, 29, 30, 31, 32, 33, 34, 35, 36, 37, 38, 39, 40, 41, 42, 43, 44, 45, 46, 47, 48, 49, 50, 51, 52, 53, 54, 55, 56, 57, 58, 59, 60, 61, 62, 63, 64, 65, 66, 67, 68, 69, 70, 71, 72, 73, 74, 75, 76, 77, 78, 79, 80, 81, 82, 83, 84, 85, 86, 87, 88, 89, 90, 92, 102

## CON100B_7
designator J?
Altium-Right: 50; Altium-Bottom: 460
footprint 50PIN-S1.27
pins: 1, 2, 3, 4, 5, 6, 7, 8, 9, 10, 11, 12, 13, 14, 15, 16, 17, 18, 19, 20, 21, 22, 23, 24, 25, 26, 27, 28, 29, 30, 31, 32, 33, 34, 35, 36, 37, 38, 39, 40, 41, 42, 43, 44, 45, 46, 47, 48, 49, 50, 51, 52, 53, 54, 55, 56, 57, 58, 59, 60, 61, 62, 63, 64, 65, 66, 67, 68, 69, 70, 71, 72, 73, 74, 75, 76, 77, 78, 79, 80, 81, 82, 83, 84, 85, 86, 87, 88, 89, 90, 91, 92

## CON_IPEX_0
designator ?, comment CON_IPEX  (value not drawn)
?; OriginalSymbolOrigin: (-100,200); Altium-Right: 40; Altium-Bottom: 80
pins: 1 IN (in), 2 GND1 (power), 3 GND2 (power)

## CONN RCPT 6_0
designator J?
Altium-Right: 31; Altium-Bottom: 50
pins: 1, 2, 3, 4, 4, 4, 4, 5, 6

## CONN RCPT 6_1
designator J?
Altium-Right: 31; Altium-Bottom: 50
pins: 1, 2, 3, 4, 5, 6

## CONN RCPT 6_2
designator J?
Altium-Right: 31; Altium-Bottom: 72
pins: 1, 2, 3, 4, 5, 6, 7, 8

## CRYSTAL-4_0
designator Y?
Altium-Right: 60; Altium-Bottom: 40
footprint CRY-3225
pins: 1 XIN, 2 GND2, 3 XOUT, 4 GND1

## CRYSTAL-4_1
designator Y?
Altium-Right: 60; Altium-Bottom: 40
footprint CRY-3225
pins: 1 XIN, 2 GND2, 3 XOUT, 4 GND1

## D2L-64-BALL-Socketed_0
designator U?, comment D2L-64-BALL-Socketed
Altium-Right: 340; Altium-Bottom: 360
footprint BGA-64-8x8-0_65MM_SOCKET
pins: A1 GND1 (power), A2 LVTX2AN, A3 LVTX2BN, A4 LVTX2CN, A5 LVTX2DN, A6 LVTX2EN, A7 GND2 (power), A8 GND3 (power), B1 VDD_L2_12 (power), B2 LVTX2AP, B3 LVTX2BP, B4 LVTX2CP, B5 LVTX2DP, B6 LVTX2EP, B7 VDD_L2_18A (power), B8 VDD_L1_12 (power), C1 GND4 (power), C2 VDDIOA (power), C3 STBY (io), C4 PWM0 (io), C5 VDD_L2_18B (power), C6 GND5 (power), C7 LVTX1AP, C8 LVTX1AN, D1 EXTCLK (in), D2 GPIO2 (io), D3 GPIO1 (io), D4 RESX (in), D5 TM (in), D6 VDD_L1_18A (power), D7 LVTX1BP, D8 LVTX1BN, E1 GND6 (power), E2 VDDCA (power), E3 GPIO0 (io), E4 VDDCB (power), E5 GND7 (power), E6 GND8 (power), E7 LVTX1CP, E8 LVTX1CN, F1 GND9 (power), F2 VDDIOB (power), F3 VDD_MIPIA (power), F4 GND10 (power), F5 GND11 (power), F6 VDD_MIPIB (power), F7 LVTX1DP, F8 LVTX1DN, G1 I2C_SCL (oc), G2 DSRXD0P, G3 DSRXD1P, G4 DSRXCP, G5 DSRXD2P, G6 DSRXD3P, G7 LVTX1EP, G8 LVTX1EN, H1 I2C_SDA (oc), H2 DSRXD0M, H3 DSRXD1M, H4 DSRXCM, H5 DSRXD2M, H6 DSRXD3M, H7 VDD_L1_18B (power), H8 GND12 (power)

## D-LED0603
designator LED?
Altium-Right: 40; Altium-Bottom: 20
pins: A ANODE, C CATHODE

## D-LED-CT
designator LED?, comment <Value>
Altium-Right: 50; Altium-Bottom: 60
pins: 1 +, 2 -, 3 E

## DCDC_SY8113_0
designator U?, comment FR9855SP  PCB Footprint: SOP8
Altium-Right: 70; Altium-Bottom: 110
pins: 1 BS, 2 LX, 3 EN, 4 SS, 5 FB, 6 VCC, 7 VIN2, 8 VIN1, 9 G-PAD

## DCDC_SY8113_1
designator U?, comment FR9855SP  PCB Footprint: SOP8
Altium-Right: 70; Altium-Bottom: 110
pins: 1 BS, 2 LX, 3 EN, 4 SS, 5 FB, 6 VCC, 7 VIN2, 8 VIN1, 9 G-PAD

## DCDC_SY8113_2
designator U?, comment FR9855SP  PCB Footprint: SOP8
Altium-Right: 70; Altium-Bottom: 110
pins: 1 BS, 2 LX, 3 EN, 4 SS, 5 FB, 6 VCC, 7 VIN2, 8 VIN1, 9 G-PAD

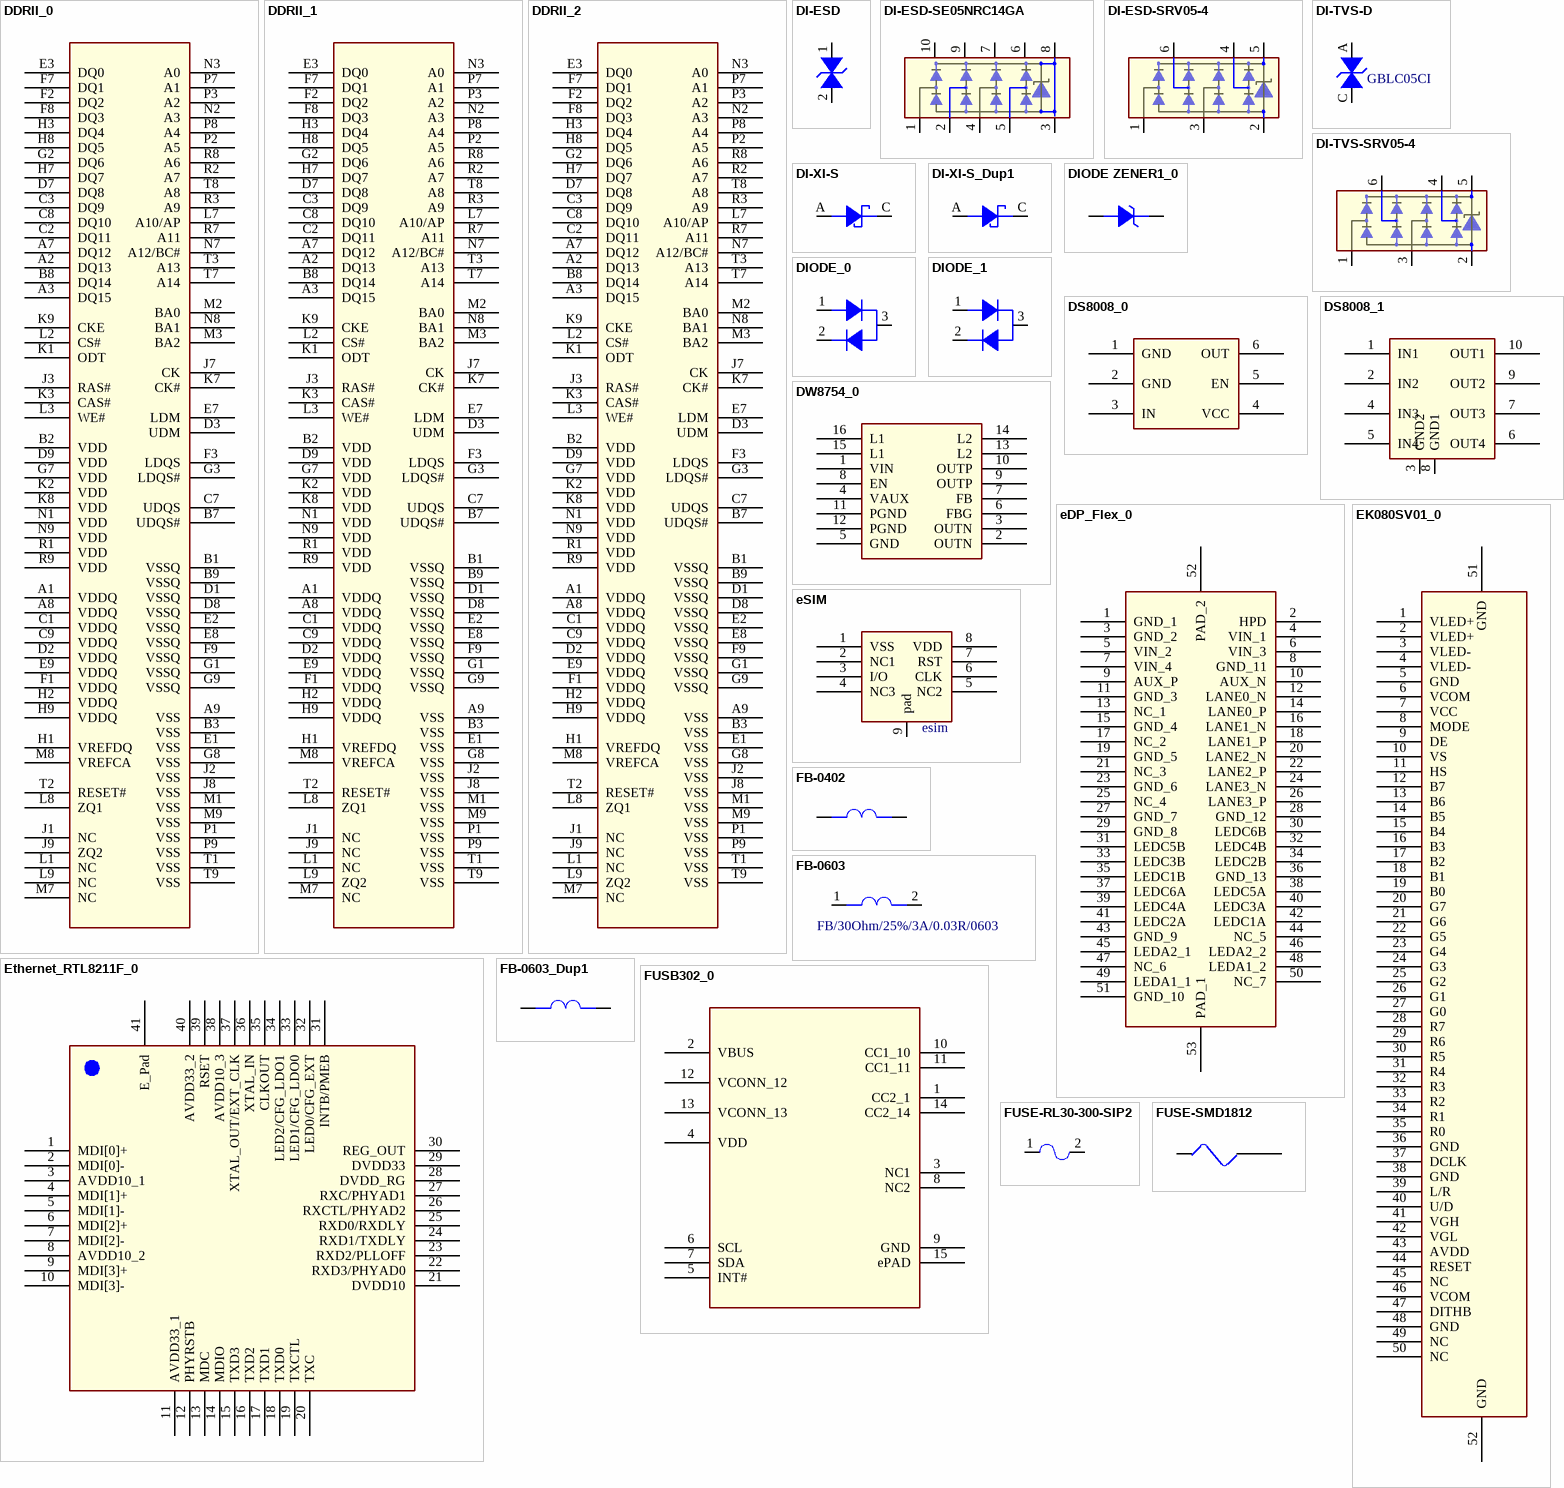
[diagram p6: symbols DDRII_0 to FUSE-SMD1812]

## DDRII_0
designator U?
Altium-Right: 80; Altium-Bottom: 590
footprint DDRII_X16
pins: A1 VDDQ, A2 DQ13, A3 DQ15, A7 DQ12, A8 VDDQ, A9 VSS, B1 VSSQ, B2 VDD, B3 VSS, B7 UDQS#, B8 DQ14, B9 VSSQ, C1 VDDQ, C2 DQ11, C3 DQ9, C7 UDQS, C8 DQ10, C9 VDDQ, D1 VSSQ, D2 VDDQ, D3 UDM, D7 DQ8, D8 VSSQ, D9 VDD, E1 VSS, E2 VSSQ, E3 DQ0, E7 LDM, E8 VSSQ, E9 VDDQ, F1 VDDQ, F2 DQ2, F3 LDQS, F7 DQ1, F8 DQ3, F9 VSSQ, G1 VSSQ, G2 DQ6, G3 LDQS#, G7 VDD, G8 VSS, G9 VSSQ, H1 VREFDQ, H2 VDDQ, H3 DQ4, H7 DQ7, H8 DQ5, H9 VDDQ, J1 NC, J2 VSS, J3 RAS#, J7 CK, J8 VSS, J9 ZQ2, K1 ODT, K2 VDD, K3 CAS#, K7 CK#, K8 VDD, K9 CKE, L1 NC, L2 CS#, L3 WE#, L7 A10/AP, L8 ZQ1, L9 NC, M1 VSS, M2 BA0, M3 BA2, M7 NC, M8 VREFCA, M9 VSS, N1 VDD, N2 A3, N3 A0, N7 A12/BC#, N8 BA1, N9 VDD, P1 VSS, P2 A5, P3 A2, P7 A1, P8 A4, P9 VSS, R1 VDD, R2 A7, R3 A9, R7 A11, R8 A6, R9 VDD, T1 VSS, T2 RESET#, T3 A13, T7 A14, T8 A8, T9 VSS

## DDRII_1
designator U?
Altium-Right: 80; Altium-Bottom: 590
footprint DDRII_X16
pins: A1 VDDQ, A2 DQ13, A3 DQ15, A7 DQ12, A8 VDDQ, A9 VSS, B1 VSSQ, B2 VDD, B3 VSS, B7 UDQS#, B8 DQ14, B9 VSSQ, C1 VDDQ, C2 DQ11, C3 DQ9, C7 UDQS, C8 DQ10, C9 VDDQ, D1 VSSQ, D2 VDDQ, D3 UDM, D7 DQ8, D8 VSSQ, D9 VDD, E1 VSS, E2 VSSQ, E3 DQ0, E7 LDM, E8 VSSQ, E9 VDDQ, F1 VDDQ, F2 DQ2, F3 LDQS, F7 DQ1, F8 DQ3, F9 VSSQ, G1 VSSQ, G2 DQ6, G3 LDQS#, G7 VDD, G8 VSS, G9 VSSQ, H1 VREFDQ, H2 VDDQ, H3 DQ4, H7 DQ7, H8 DQ5, H9 VDDQ, J1 NC, J2 VSS, J3 RAS#, J7 CK, J8 VSS, J9 NC, K1 ODT, K2 VDD, K3 CAS#, K7 CK#, K8 VDD, K9 CKE, L1 NC, L2 CS#, L3 WE#, L7 A10/AP, L8 ZQ1, L9 ZQ2, M1 VSS, M2 BA0, M3 BA2, M7 NC, M8 VREFCA, M9 VSS, N1 VDD, N2 A3, N3 A0, N7 A12/BC#, N8 BA1, N9 VDD, P1 VSS, P2 A5, P3 A2, P7 A1, P8 A4, P9 VSS, R1 VDD, R2 A7, R3 A9, R7 A11, R8 A6, R9 VDD, T1 VSS, T2 RESET#, T3 A13, T7 A14, T8 A8, T9 VSS

## DDRII_2
designator U?
Altium-Right: 80; Altium-Bottom: 590
footprint DDRII_X16
pins: A1 VDDQ, A2 DQ13, A3 DQ15, A7 DQ12, A8 VDDQ, A9 VSS, B1 VSSQ, B2 VDD, B3 VSS, B7 UDQS#, B8 DQ14, B9 VSSQ, C1 VDDQ, C2 DQ11, C3 DQ9, C7 UDQS, C8 DQ10, C9 VDDQ, D1 VSSQ, D2 VDDQ, D3 UDM, D7 DQ8, D8 VSSQ, D9 VDD, E1 VSS, E2 VSSQ, E3 DQ0, E7 LDM, E8 VSSQ, E9 VDDQ, F1 VDDQ, F2 DQ2, F3 LDQS, F7 DQ1, F8 DQ3, F9 VSSQ, G1 VSSQ, G2 DQ6, G3 LDQS#, G7 VDD, G8 VSS, G9 VSSQ, H1 VREFDQ, H2 VDDQ, H3 DQ4, H7 DQ7, H8 DQ5, H9 VDDQ, J1 NC, J2 VSS, J3 RAS#, J7 CK, J8 VSS, J9 NC, K1 ODT, K2 VDD, K3 CAS#, K7 CK#, K8 VDD, K9 CKE, L1 NC, L2 CS#, L3 WE#, L7 A10/AP, L8 ZQ1, L9 ZQ2, M1 VSS, M2 BA0, M3 BA2, M7 NC, M8 VREFCA, M9 VSS, N1 VDD, N2 A3, N3 A0, N7 A12/BC#, N8 BA1, N9 VDD, P1 VSS, P2 A5, P3 A2, P7 A1, P8 A4, P9 VSS, R1 VDD, R2 A7, R3 A9, R7 A11, R8 A6, R9 VDD, T1 VSS, T2 RESET#, T3 A13, T7 A14, T8 A8, T9 VSS

## DI-ESD
designator T?
ESD 0402; Part Number: EB3.1R0UV18402A; Manufacture P/N: MLVG04021R0UV18; Manufacturer: INPAQ; PN Type: Varistor; Altium-Right: 20
pins: 1 I/O2, 2 I/O1

## DI-ESD-SE05NRC14GA
designator D?
Altium-Right: 110; Altium-Bottom: 40
pins: 1, 2, 3, 4, 5, 6, 7, 8, 9, 10

## DI-ESD-SRV05-4
designator D?
Altium-Right: 100; Altium-Bottom: 40
pins: 1, 2, 3, 4, 5, 6

## DI-TVS-D
designator T?, comment GBLC05CI
ESD 0402; Manufacturer: INPAQ; Manufacture P/N: MLVG04021R0UV18; Part Number: EB3.1R0UV18402A; PN Type: Varistor; Altium-Right: 20
pins: A I/O2, C I/O1

## DI-TVS-SRV05-4
designator D?
Altium-Right: 100; Altium-Bottom: 40
pins: 1, 2, 3, 4, 5, 6

## DI-XI-S
designator D?
CLASS: IC; Altium-Right: 30; Altium-Bottom: 20
pins: A, C

## DI-XI-S_Dup1
designator D?
CLASS: IC; Altium-Right: 30; Altium-Bottom: 20
pins: A, C

## DIODE ZENER1_0
designator D?
Altium-Right: 30; Altium-Bottom: 20
pins: 1 CATHODE, 2 ANODE

## DIODE_0
designator D?
Altium-Right: 30; Altium-Bottom: 40
pins: 1 ANODE, 2 CATHODE, 3 COMMON

## DIODE_1
designator D?
Altium-Right: 30; Altium-Bottom: 40
pins: 1 ANODE, 2 CATHODE, 3 COMMON

## DS8008_0
designator U?
Altium-Right: 70; Altium-Bottom: 60
pins: 1 GND, 2 GND, 3 IN, 4 VCC, 5 EN, 6 OUT

## DS8008_1
designator U?
Altium-Right: 70; Altium-Bottom: 80
pins: 1 IN1, 2 IN2, 3 GND2, 4 IN3, 5 IN4, 6 OUT4, 7 OUT3, 8 GND1, 9 OUT2, 10 OUT1

## DW8754_0
designator U?
Altium-Right: 80; Altium-Bottom: 90
footprint UDFN12
pins: 1 VIN, 2 OUTN, 3 OUTN, 4 VAUX, 5 GND, 6 FBG, 7 FB, 8 EN, 9 OUTP, 10 OUTP, 11 PGND, 12 PGND, 13 L2, 14 L2, 15 L1, 16 L1

## eDP_Flex_0
designator J?
Altium-Right: 100; Altium-Bottom: 290
pins: 1 GND_1, 2 HPD, 3 GND_2, 4 VIN_1, 5 VIN_2, 6 VIN_3, 7 VIN_4, 8 GND_11, 9 AUX_P, 10 AUX_N, 11 GND_3, 12 LANE0_N, 13 NC_1, 14 LANE0_P, 15 GND_4, 16 LANE1_N, 17 NC_2, 18 LANE1_P, 19 GND_5, 20 LANE2_N, 21 NC_3, 22 LANE2_P, 23 GND_6, 24 LANE3_N, 25 NC_4, 26 LANE3_P, 27 GND_7, 28 GND_12, 29 GND_8, 30 LEDC6B, 31 LEDC5B, 32 LEDC4B, 33 LEDC3B, 34 LEDC2B, 35 LEDC1B, 36 GND_13, 37 LEDC6A, 38 LEDC5A, 39 LEDC4A, 40 LEDC3A, 41 LEDC2A, 42 LEDC1A, 43 GND_9, 44 NC_5, 45 LEDA2_1, 46 LEDA2_2, 47 NC_6, 48 LEDA1_2, 49 LEDA1_1, 50 NC_7, 51 GND_10, 52 PAD_2, 53 PAD_1

## EK080SV01_0
designator J?
Altium-Right: 70; Altium-Bottom: 550
pins: 1 VLED+, 2 VLED+, 3 VLED-, 4 VLED-, 5 GND, 6 VCOM, 7 VCC, 8 MODE, 9 DE, 10 VS, 11 HS, 12 B7, 13 B6, 14 B5, 15 B4, 16 B3, 17 B2, 18 B1, 19 B0, 20 G7, 21 G6, 22 G5, 23 G4, 24 G3, 25 G2, 26 G1, 27 G0, 28 R7, 29 R6, 30 R5, 31 R4, 32 R3, 33 R2, 34 R1, 35 R0, 36 GND, 37 DCLK, 38 GND, 39 L/R, 40 U/D, 41 VGH, 42 VGL, 43 AVDD, 44 RESET, 45 NC, 46 VCOM, 47 DITHB, 48 GND, 49 NC, 50 NC, 51 GND, 52 GND

## eSIM
designator U?, comment esim
Altium-Right: 60
footprint eSIM
pins: 1 VSS, 2 NC1, 3 I/O, 4 NC3, 5 NC2, 6 CLK, 7 RST, 8 VDD, 9 pad

## Ethernet_RTL8211F_0
designator U?
Altium-Right: 230
footprint QFN40_5R00X5R00X0R80_T
pins: 1 MDI[0]+, 2 MDI[0]-, 3 AVDD10_1 (power), 4 MDI[1]+, 5 MDI[1]-, 6 MDI[2]+, 7 MDI[2]-, 8 AVDD10_2 (power), 9 MDI[3]+, 10 MDI[3]-, 11 AVDD33_1 (power), 12 PHYRSTB, 13 MDC, 14 MDIO, 15 TXD3, 16 TXD2, 17 TXD1, 18 TXD0, 19 TXCTL, 20 TXC, 21 DVDD10 (power), 22 RXD3/PHYAD0, 23 RXD2/PLLOFF, 24 RXD1/TXDLY, 25 RXD0/RXDLY, 26 RXCTL/PHYAD2, 27 RXC/PHYAD1, 28 DVDD_RG, 29 DVDD33 (power), 30 REG_OUT, 31 INTB/PMEB, 32 LED0/CFG_EXT, 33 LED1/CFG_LDO0, 34 LED2/CFG_LDO1, 35 CLKOUT, 36 XTAL_IN, 37 XTAL_OUT/EXT_CLK, 38 AVDD10_3 (power), 39 RSET, 40 AVDD33_2 (power), 41 E_Pad

## FB-0402
designator FB?
SMD Multilayer Ferrite Chip Bead,3A,30Ohm,0.03R; Manufacturer: SUNLORD; Manufacture2 P/N: PBY160808T-400Y-N; Manufacture P/N: PZ1608D300-3R0TF; Part Number: EL4.300Y060300A; PN Type: SMD FERRITE BEAD; Altium-Right: 40; Altium-Bottom: 20
pins: 1, 2

## FB-0603
designator FB?, comment FB/30Ohm/25%/3A/0.03R/0603
SMD Multilayer Ferrite Chip Bead,3A,30Ohm,0.03R; Part Number: EL4.300Y060300A; Manufacture P/N: PZ1608D300-3R0TF; Manufacture2 P/N: PBY160808T-400Y-N; Manufacturer: SUNLORD; PN Type: SMD FERRITE BEAD; Altium-Right: 40; Altium-Bottom: 20
pins: 1, 2

## FB-0603_Dup1
designator FB?
SMD Multilayer Ferrite Chip Bead,3A,30Ohm,0.03R; Manufacturer: SUNLORD; Manufacture2 P/N: PBY160808T-400Y-N; Manufacture P/N: PZ1608D300-3R0TF; Part Number: EL4.300Y060300A; PN Type: SMD FERRITE BEAD; Altium-Right: 40; Altium-Bottom: 20
pins: 1, 2

## FUSB302_0
designator U?
Altium-Right: 140; Altium-Bottom: 200
footprint MLP14_2R50X2R50X0R80
pins: 1 CC2_1, 2 VBUS, 3 NC1, 4 VDD, 5 INT#, 6 SCL, 7 SDA, 8 NC2, 9 GND, 10 CC1_10, 11 CC1_11, 12 VCONN_12, 13 VCONN_13, 14 CC2_14, 15 ePAD

## FUSE-RL30-300-SIP2
designator F?
Altium-Right: 20
footprint FUSE-DIP-600
pins: 1, 2

## FUSE-SMD1812
designator F?
Altium-Right: 30; Altium-Bottom: 20
pins: 1, 2

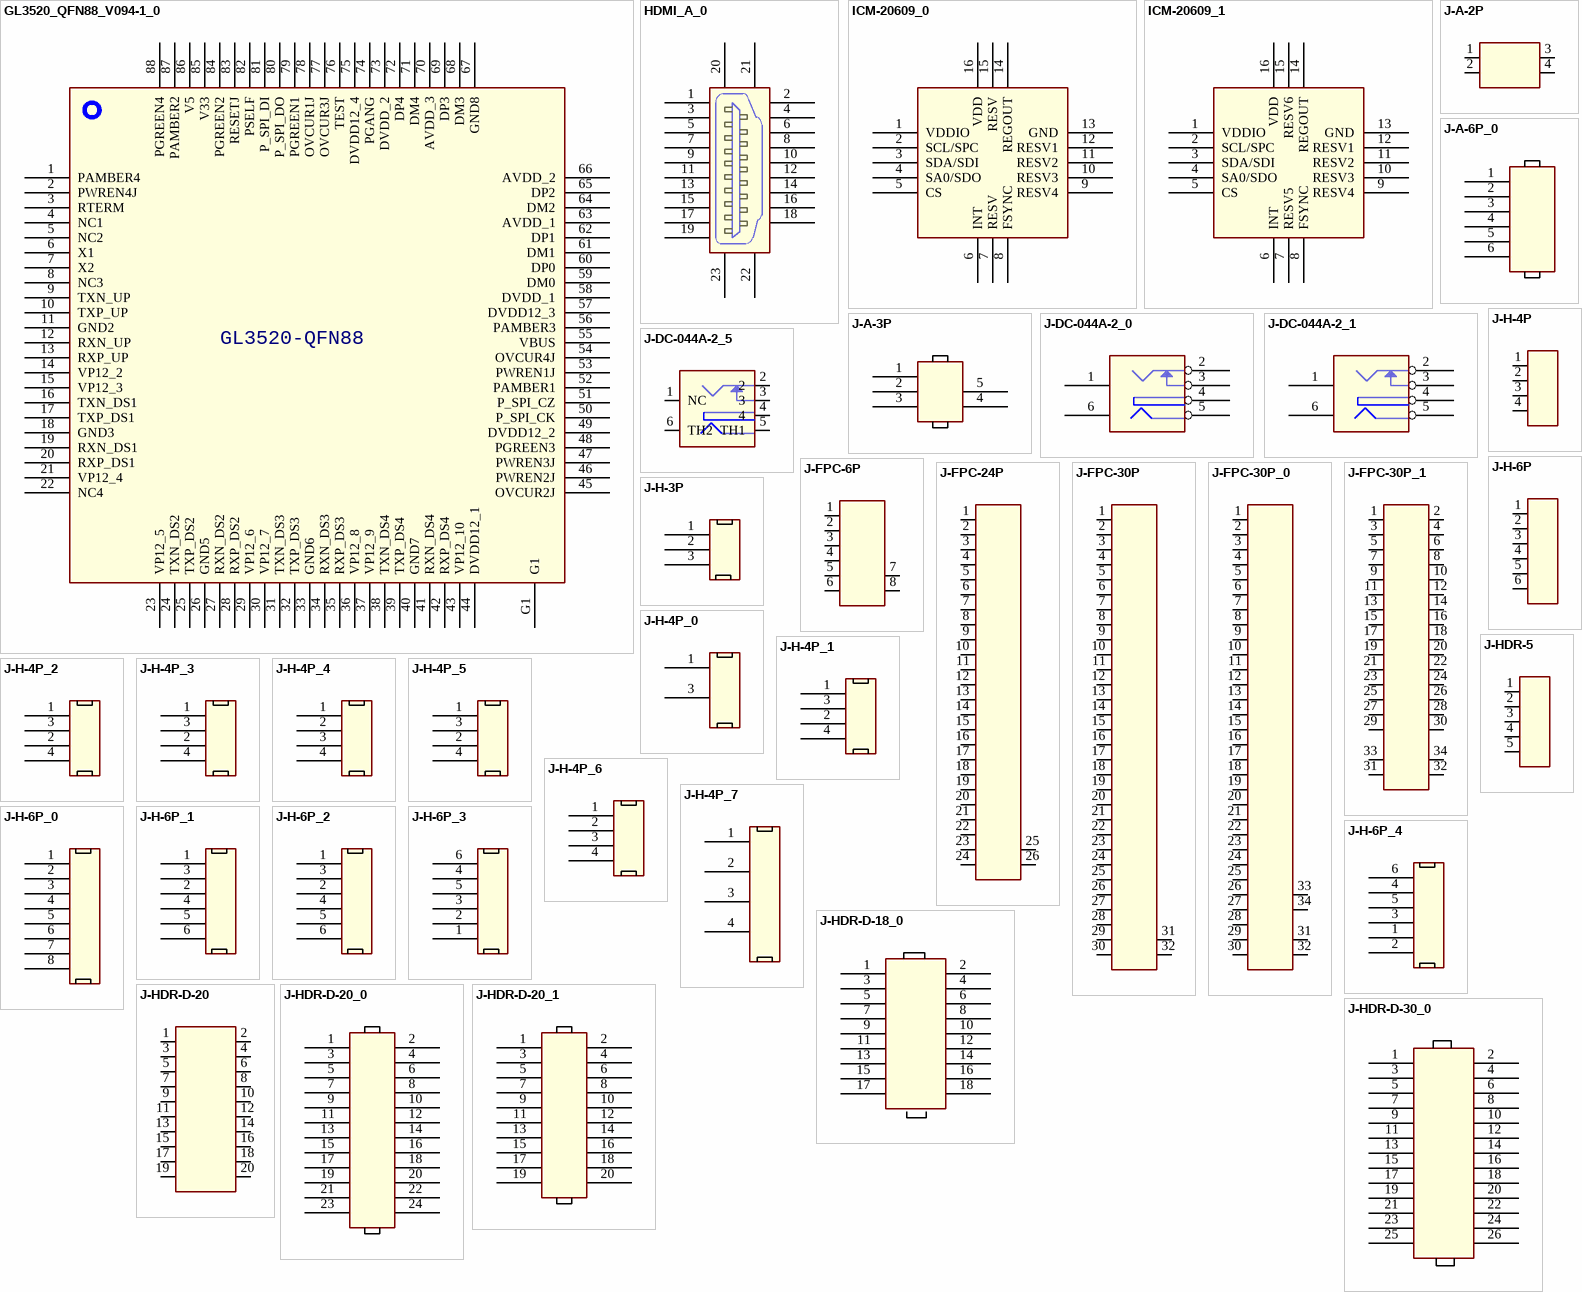
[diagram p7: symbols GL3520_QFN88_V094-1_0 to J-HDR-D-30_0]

## GL3520_QFN88_V094-1_0
designator U?  (value not drawn)
Altium-Right: 330
footprint I-LQFP128-0_4A
pins: 1 PAMBER4, 2 PWREN4J, 3 RTERM, 4 NC1, 5 NC2, 6 X1, 7 X2, 8 NC3, 9 TXN_UP, 10 TXP_UP, 11 GND2, 12 RXN_UP, 13 RXP_UP, 14 VP12_2, 15 VP12_3, 16 TXN_DS1, 17 TXP_DS1, 18 GND3, 19 RXN_DS1, 20 RXP_DS1, 21 VP12_4, 22 NC4, 23 VP12_5, 24 TXN_DS2, 25 TXP_DS2, 26 GND5, 27 RXN_DS2, 28 RXP_DS2, 29 VP12_6, 30 VP12_7, 31 TXN_DS3, 32 TXP_DS3, 33 GND6, 34 RXN_DS3, 35 RXP_DS3, 36 VP12_8, 37 VP12_9, 38 TXN_DS4, 39 TXP_DS4, 40 GND7, 41 RXN_DS4, 42 RXP_DS4, 43 VP12_10, 44 DVDD12_1, 45 OVCUR2J, 46 PWREN2J, 47 PWREN3J, 48 PGREEN3, 49 DVDD12_2, 50 P_SPI_CK, 51 P_SPI_CZ, 52 PAMBER1, 53 PWREN1J, 54 OVCUR4J, 55 VBUS, 56 PAMBER3, 57 DVDD12_3, 58 DVDD_1, 59 DM0, 60 DP0, 61 DM1, 62 DP1, 63 AVDD_1, 64 DM2, 65 DP2, 66 AVDD_2, 67 GND8, 68 DM3, 69 DP3, 70 AVDD_3, 71 DM4, 72 DP4, 73 DVDD_2, 74 PGANG, 75 DVDD12_4, 76 TEST, 77 OVCUR3J, 78 OVCUR1J, 79 PGREEN1, 80 P_SPI_DO, 81 P_SPI_DI, 82 PSELF, 83 RESETJ, 84 PGREEN2, 85 V33, 86 V5, 87 PAMBER2, 88 PGREEN4, G1

## HDMI_A_0
designator J?
Altium-Right: 40; Altium-Bottom: 110
pins: 1 $PIN0, 2, 3, 4, 5, 6, 7, 8, 9, 10, 11, 12, 13, 14, 15, 16, 17, 18, 19, 20, 21, 22, 23

## ICM-20609_0
designator U?
Altium-Right: 100
pins: 1 VDDIO, 2 SCL/SPC, 3 SDA/SDI, 4 SA0/SDO, 5 CS, 6 INT, 7 RESV, 8 FSYNC, 9 RESV4, 10 RESV3, 11 RESV2, 12 RESV1, 13 GND, 14 REGOUT, 15 RESV, 16 VDD

## ICM-20609_1
designator U?
Altium-Right: 100
pins: 1 VDDIO, 2 SCL/SPC, 3 SDA/SDI, 4 SA0/SDO, 5 CS, 6 INT, 7 RESV5, 8 FSYNC, 9 RESV4, 10 RESV3, 11 RESV2, 12 RESV1, 13 GND, 14 REGOUT, 15 RESV6, 16 VDD

## J-A-2P
designator J?
Altium-Right: 40; Altium-Bottom: 30
pins: 1, 2, 3, 4

## J-A-3P
designator J?
Altium-Right: 30; Altium-Bottom: 60
pins: 1, 2, 3, 4, 5

## J-A-6P_0
designator J?
Altium-Right: 30; Altium-Bottom: 90
pins: 1 2, 2 4, 3 6, 4 8, 5 10, 6 12

## J-DC-044A-2_0
designator J?
Altium-Right: 50; Altium-Bottom: 51
pins: 1, 2, 3, 4, 5, 6

## J-DC-044A-2_1
designator J?
Altium-Right: 50; Altium-Bottom: 51
pins: 1, 2, 3, 4, 5, 6

## J-DC-044A-2_5
designator J?
Altium-Right: 50; Altium-Bottom: 51
pins: 1 NC, 2, 3, 4, 5 TH1, 6 TH2

## J-FPC-6P
designator J?
Altium-Right: 30; Altium-Bottom: 70
pins: 1, 2, 3, 4, 5, 6, 7, 8

## J-FPC-24P
designator J?
Altium-Right: 30; Altium-Bottom: 250
pins: 1, 2, 3, 4, 5, 6, 7, 8, 9, 10, 11, 12, 13, 14, 15, 16, 17, 18, 19, 20, 21, 22, 23, 24, 25, 26

## J-FPC-30P
designator J?
Altium-Right: 30; Altium-Bottom: 310
pins: 1, 2, 3, 4, 5, 6, 7, 8, 9, 10, 11, 12, 13, 14, 15, 16, 17, 18, 19, 20, 21, 22, 23, 24, 25, 26, 27, 28, 29, 30, 31, 32

## J-FPC-30P_0
designator J?
Altium-Right: 30; Altium-Bottom: 310
pins: 1, 2, 3, 4, 5, 6, 7, 8, 9, 10, 11, 12, 13, 14, 15, 16, 17, 18, 19, 20, 21, 22, 23, 24, 25, 26, 27, 28, 29, 30, 31, 32, 33, 34

## J-FPC-30P_1
designator J?
Altium-Right: 30; Altium-Bottom: 190
pins: 1, 2, 3, 4, 5, 6, 7, 8, 9, 10, 11, 12, 13, 14, 15, 16, 17, 18, 19, 20, 21, 22, 23, 24, 25, 26, 27, 28, 29, 30, 31, 32, 33, 34

## J-H-3P
designator J?
Altium-Right: 20; Altium-Bottom: 40
pins: 1 3, 2, 3 1

## J-H-4P
designator J?
Altium-Right: 20; Altium-Bottom: 50
pins: 1, 2, 3, 4

## J-H-4P_0
designator J?
Altium-Right: 20; Altium-Bottom: 50
pins: 1, 3

## J-H-4P_1
designator J?
Altium-Right: 20; Altium-Bottom: 50
pins: 1, 2, 3, 4

## J-H-4P_2
designator J?
Altium-Right: 20; Altium-Bottom: 50
pins: 1, 2, 3, 4

## J-H-4P_3
designator J?
Altium-Right: 20; Altium-Bottom: 50
pins: 1, 2, 3, 4

## J-H-4P_4
designator J?
Altium-Right: 20; Altium-Bottom: 50
pins: 1, 2, 3, 4

## J-H-4P_5
designator J?
Altium-Right: 20; Altium-Bottom: 50
pins: 1, 2, 3, 4

## J-H-4P_6
designator J?
Altium-Right: 20; Altium-Bottom: 50
pins: 1, 2, 3, 4

## J-H-4P_7
designator J?
Altium-Right: 20; Altium-Bottom: 90
pins: 1, 2, 3, 4

## J-H-6P
designator J?
Altium-Right: 20; Altium-Bottom: 70
pins: 1, 2, 3, 4, 5, 6

## J-H-6P_0
designator J?
Altium-Right: 20; Altium-Bottom: 90
pins: 1, 2, 3, 4, 5, 6, 7, 8

## J-H-6P_1
designator J?
Altium-Right: 20; Altium-Bottom: 70
pins: 1, 2, 3, 4, 5, 6

## J-H-6P_2
designator J?
Altium-Right: 20; Altium-Bottom: 70
pins: 1, 2, 3, 4, 5, 6

## J-H-6P_3
designator J?
Altium-Right: 20; Altium-Bottom: 70
pins: 1, 2, 3, 4, 5, 6

## J-H-6P_4
designator J?
Altium-Right: 20; Altium-Bottom: 70
pins: 1, 2, 3, 4, 5, 6

## J-HDR-5
designator J?
Altium-Right: 20; Altium-Bottom: 60
pins: 1, 2, 3, 4, 5

## J-HDR-D-18_0
designator J?
Altium-Right: 40; Altium-Bottom: 116
pins: 1, 2, 3, 4, 5, 6 06, 7 07, 8 08, 9, 10, 11, 12, 13, 14, 15, 16, 17, 18

## J-HDR-D-20
designator J?
Altium-Right: 40; Altium-Bottom: 110
pins: 1, 2, 3, 4, 5, 6, 7, 8, 9, 10, 11, 12, 13, 14, 15, 16, 17, 18, 19, 20

## J-HDR-D-20_0
designator J?
Altium-Right: 30; Altium-Bottom: 144
pins: 1, 2, 3, 4, 5, 6, 7, 8, 9, 10, 11, 12, 13, 14, 15, 16, 17, 18, 19, 20, 21, 22, 23, 24

## J-HDR-D-20_1
designator J?
Altium-Right: 30; Altium-Bottom: 130
pins: 1, 2, 3, 4, 5, 6, 7, 8, 9, 10, 11, 12, 13, 14, 15, 16, 17, 18, 19, 20

## J-HDR-D-30_0
designator J?
Altium-Right: 40; Altium-Bottom: 155
pins: 1, 2 16, 3 2, 4 17, 5 3, 6 18, 7 4, 8 19, 9 5, 10 20, 11 6, 12 21, 13 7, 14 22, 15 8, 16 23, 17 9, 18 24, 19 10, 20 25, 21 11, 22 26, 23 12, 24 27, 25 13, 26 28

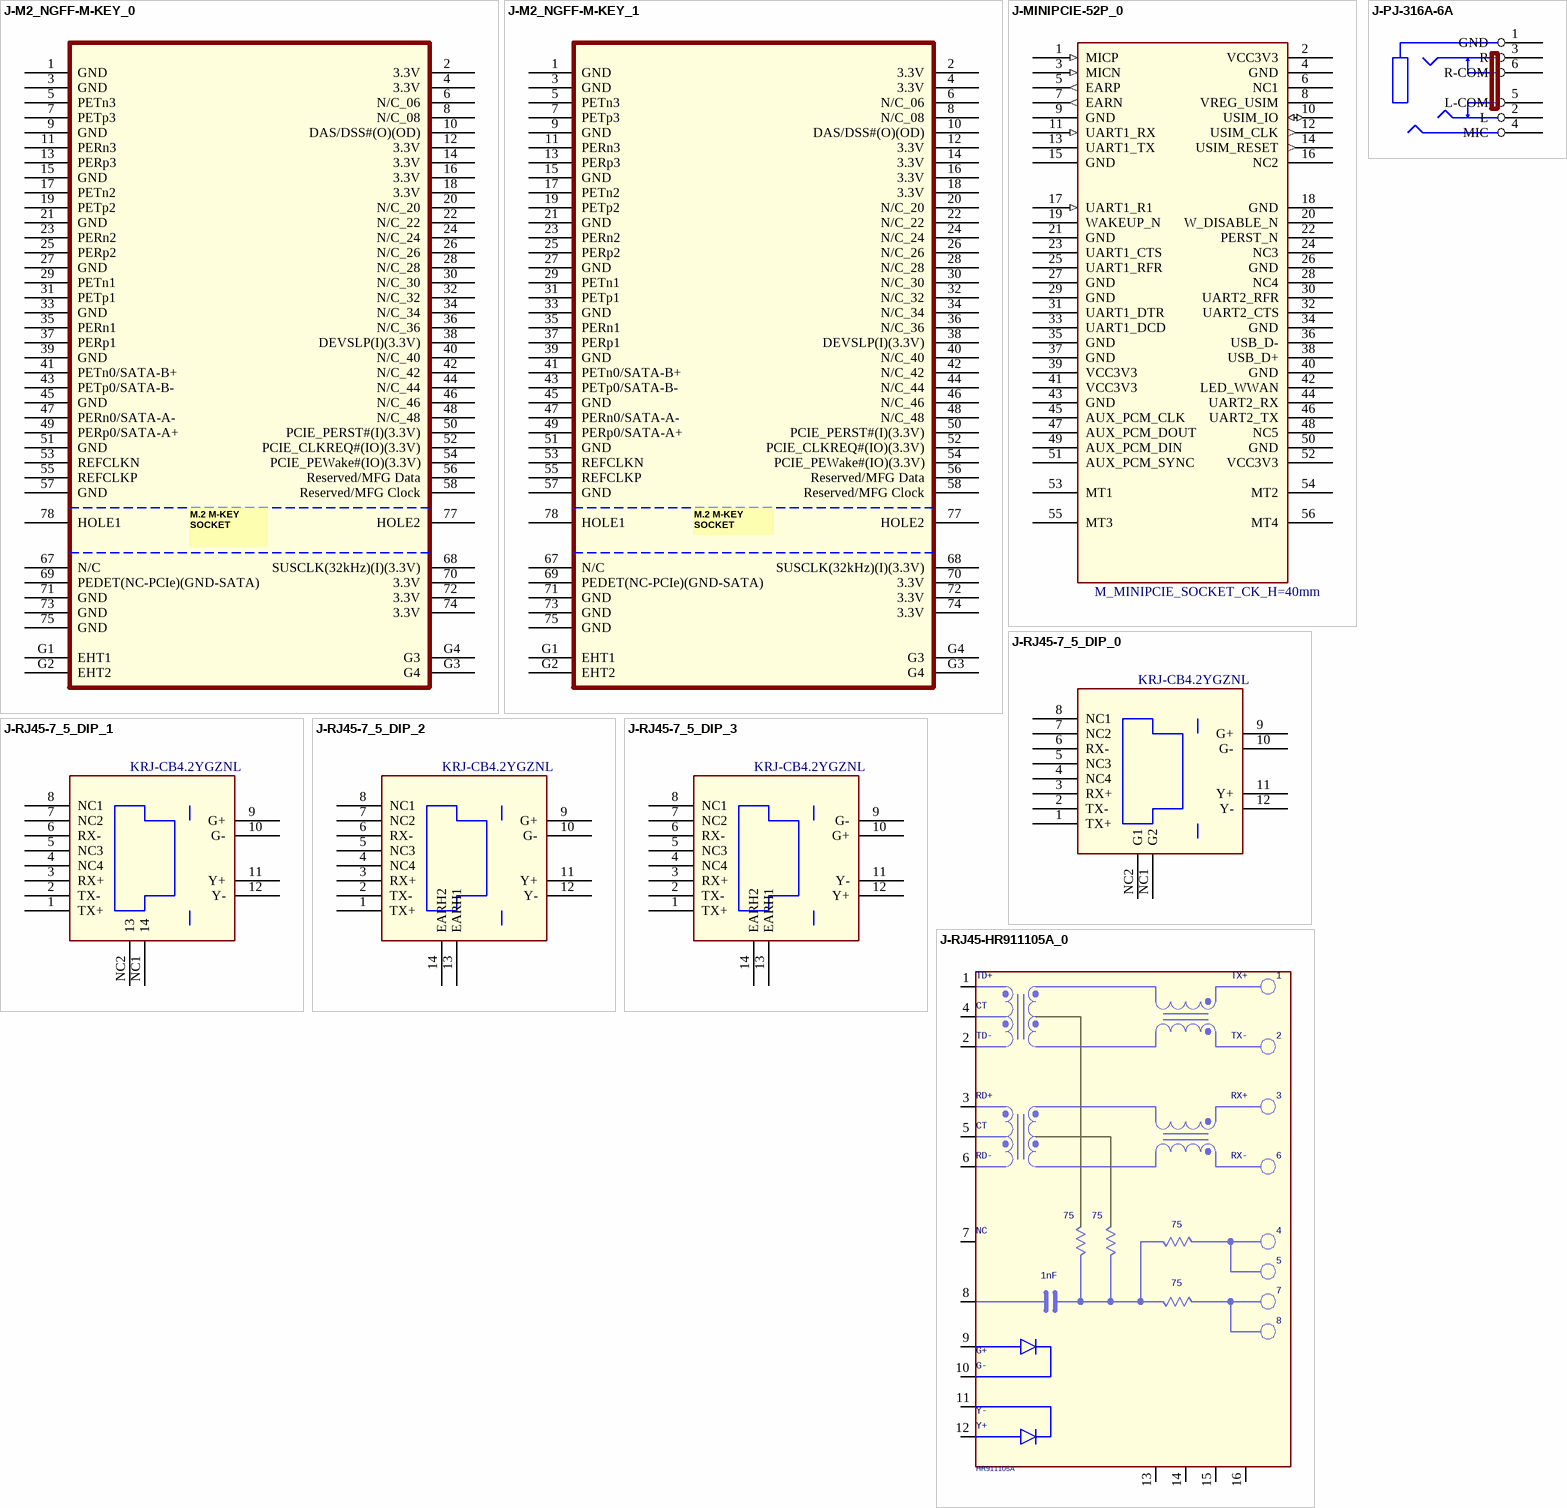
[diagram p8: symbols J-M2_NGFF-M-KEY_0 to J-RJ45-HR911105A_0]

## J-M2_NGFF-M-KEY_0
designator J?
Altium-Right: 240; Altium-Bottom: 430
pins: 1 GND (power), 2 3.3V (power), 3 GND (power), 4 3.3V (power), 5 PETn3, 6 N/C_06, 7 PETp3, 8 N/C_08, 9 GND (power), 10 DAS/DSS#(O)(OD), 11 PERn3, 12 3.3V (power), 13 PERp3, 14 3.3V (power), 15 GND (power), 16 3.3V (power), 17 PETn2, 18 3.3V (power), 19 PETp2, 20 N/C_20, 21 GND (power), 22 N/C_22, 23 PERn2, 24 N/C_24, 25 PERp2, 26 N/C_26, 27 GND (power), 28 N/C_28, 29 PETn1, 30 N/C_30, 31 PETp1, 32 N/C_32, 33 GND (power), 34 N/C_34, 35 PERn1, 36 N/C_36, 37 PERp1, 38 DEVSLP(I)(3.3V), 39 GND (power), 40 N/C_40, 41 PETn0/SATA-B+, 42 N/C_42, 43 PETp0/SATA-B-, 44 N/C_44, 45 GND (power), 46 N/C_46, 47 PERn0/SATA-A-, 48 N/C_48, 49 PERp0/SATA-A+, 50 PCIE_PERST#(I)(3.3V), 51 GND (power), 52 PCIE_CLKREQ#(IO)(3.3V), 53 REFCLKN, 54 PCIE_PEWake#(IO)(3.3V), 55 REFCLKP, 56 Reserved/MFG Data, 57 GND (power), 58 Reserved/MFG Clock, 67 N/C, 68 SUSCLK(32kHz)(I)(3.3V), 69 PEDET(NC-PCIe)(GND-SATA), 70 3.3V (power), 71 GND (power), 72 3.3V (power), 73 GND (power), 74 3.3V (power), 75 GND (power), 77 HOLE2 (power), 78 HOLE1 (power), G1 EHT1, G2 EHT2, G3 G4, G4 G3

## J-M2_NGFF-M-KEY_1
designator J?
Altium-Right: 240; Altium-Bottom: 430
pins: 1 GND (power), 2 3.3V (power), 3 GND (power), 4 3.3V (power), 5 PETn3, 6 N/C_06, 7 PETp3, 8 N/C_08, 9 GND (power), 10 DAS/DSS#(O)(OD), 11 PERn3, 12 3.3V (power), 13 PERp3, 14 3.3V (power), 15 GND (power), 16 3.3V (power), 17 PETn2, 18 3.3V (power), 19 PETp2, 20 N/C_20, 21 GND (power), 22 N/C_22, 23 PERn2, 24 N/C_24, 25 PERp2, 26 N/C_26, 27 GND (power), 28 N/C_28, 29 PETn1, 30 N/C_30, 31 PETp1, 32 N/C_32, 33 GND (power), 34 N/C_34, 35 PERn1, 36 N/C_36, 37 PERp1, 38 DEVSLP(I)(3.3V), 39 GND (power), 40 N/C_40, 41 PETn0/SATA-B+, 42 N/C_42, 43 PETp0/SATA-B-, 44 N/C_44, 45 GND (power), 46 N/C_46, 47 PERn0/SATA-A-, 48 N/C_48, 49 PERp0/SATA-A+, 50 PCIE_PERST#(I)(3.3V), 51 GND (power), 52 PCIE_CLKREQ#(IO)(3.3V), 53 REFCLKN, 54 PCIE_PEWake#(IO)(3.3V), 55 REFCLKP, 56 Reserved/MFG Data, 57 GND (power), 58 Reserved/MFG Clock, 67 N/C, 68 SUSCLK(32kHz)(I)(3.3V), 69 PEDET(NC-PCIe)(GND-SATA), 70 3.3V (power), 71 GND (power), 72 3.3V (power), 73 GND (power), 74 3.3V (power), 75 GND (power), 77 HOLE2, 78 HOLE1, G1 EHT1, G2 EHT2, G3 G4, G4 G3

## J-MINIPCIE-52P_0
designator MINI-PCIE?, comment M_MINIPCIE_SOCKET_CK_H=40mm
CLASS: IO; Altium-Right: 140; Altium-Bottom: 360
pins: 1 MICP (in), 2 VCC3V3 (power), 3 MICN (in), 4 GND (power), 5 EARP (out), 6 NC1, 7 EARN (out), 8 VREG_USIM (power), 9 GND (power), 10 USIM_IO (io), 11 UART1_RX (in), 12 USIM_CLK (out), 13 UART1_TX, 14 USIM_RESET (out), 15 GND (power), 16 NC2, 17 UART1_R1 (in), 18 GND (power), 19 WAKEUP_N, 20 W_DISABLE_N, 21 GND (power), 22 PERST_N, 23 UART1_CTS, 24 NC3, 25 UART1_RFR, 26 GND (power), 27 GND (power), 28 NC4, 29 GND (power), 30 UART2_RFR, 31 UART1_DTR, 32 UART2_CTS, 33 UART1_DCD, 34 GND (power), 35 GND (power), 36 USB_D-, 37 GND (power), 38 USB_D+, 39 VCC3V3 (power), 40 GND (power), 41 VCC3V3 (power), 42 LED_WWAN, 43 GND (power), 44 UART2_RX, 45 AUX_PCM_CLK, 46 UART2_TX, 47 AUX_PCM_DOUT, 48 NC5, 49 AUX_PCM_DIN, 50 GND (power), 51 AUX_PCM_SYNC, 52 VCC3V3 (power), 53 MT1, 54 MT2, 55 MT3, 56 MT4

## J-PJ-316A-6A
designator J?
Altium-Right: 70; Altium-Bottom: 60
pins: 1 GND, 2 L, 3 R, 4 MIC, 5 L-COM, 6 R-COM

## J-RJ45-7_5_DIP_0
designator RJ45?, comment KRJ-CB4.2YGZNL
Altium-Right: 110
pins: 1 TX+, 2 TX-, 3 RX+, 4 NC4, 5 NC3, 6 RX-, 7 NC2, 8 NC1, 9 G+, 10 G-, 11 Y+, 12 Y-, NC1 G2, NC2 G1

## J-RJ45-7_5_DIP_1
designator RJ45?, comment KRJ-CB4.2YGZNL
Altium-Right: 110
pins: 1 TX+, 2 TX-, 3 RX+, 4 NC4, 5 NC3, 6 RX-, 7 NC2, 8 NC1, 9 G+, 10 G-, 11 Y+, 12 Y-, NC1 14, NC2 13

## J-RJ45-7_5_DIP_2
designator RJ45?, comment KRJ-CB4.2YGZNL
Altium-Right: 110
pins: 1 TX+, 2 TX-, 3 RX+, 4 NC4, 5 NC3, 6 RX-, 7 NC2, 8 NC1, 9 G+, 10 G-, 11 Y+, 12 Y-, 13 EARH1, 14 EARH2

## J-RJ45-7_5_DIP_3
designator RJ45?, comment KRJ-CB4.2YGZNL
Altium-Right: 110
pins: 1 TX+, 2 TX-, 3 RX+, 4 NC4, 5 NC3, 6 RX-, 7 NC2, 8 NC1, 9 G-, 10 G+, 11 Y-, 12 Y+, 13 EARH1, 14 EARH2

## J-RJ45-HR911105A_0
designator RJ45?  VAL: HR911105A  (hidden comment: *)
REF: J00-0061; DESIG: 10/100 base TX LXT971A; BOI: RJ45; FAB: PULSE; DEV: CON_PULSE_J00-61; Altium-Right: 210; Altium-Bottom: 330
pins: 1 P1, 2 P2, 3 P3, 4 P4, 5 P5, 6 P6, 7 P7, 8 P8, 9 G+, 10 G-, 11 Y-, 12 Y+, 13 P13, 14 P14, 15, 16

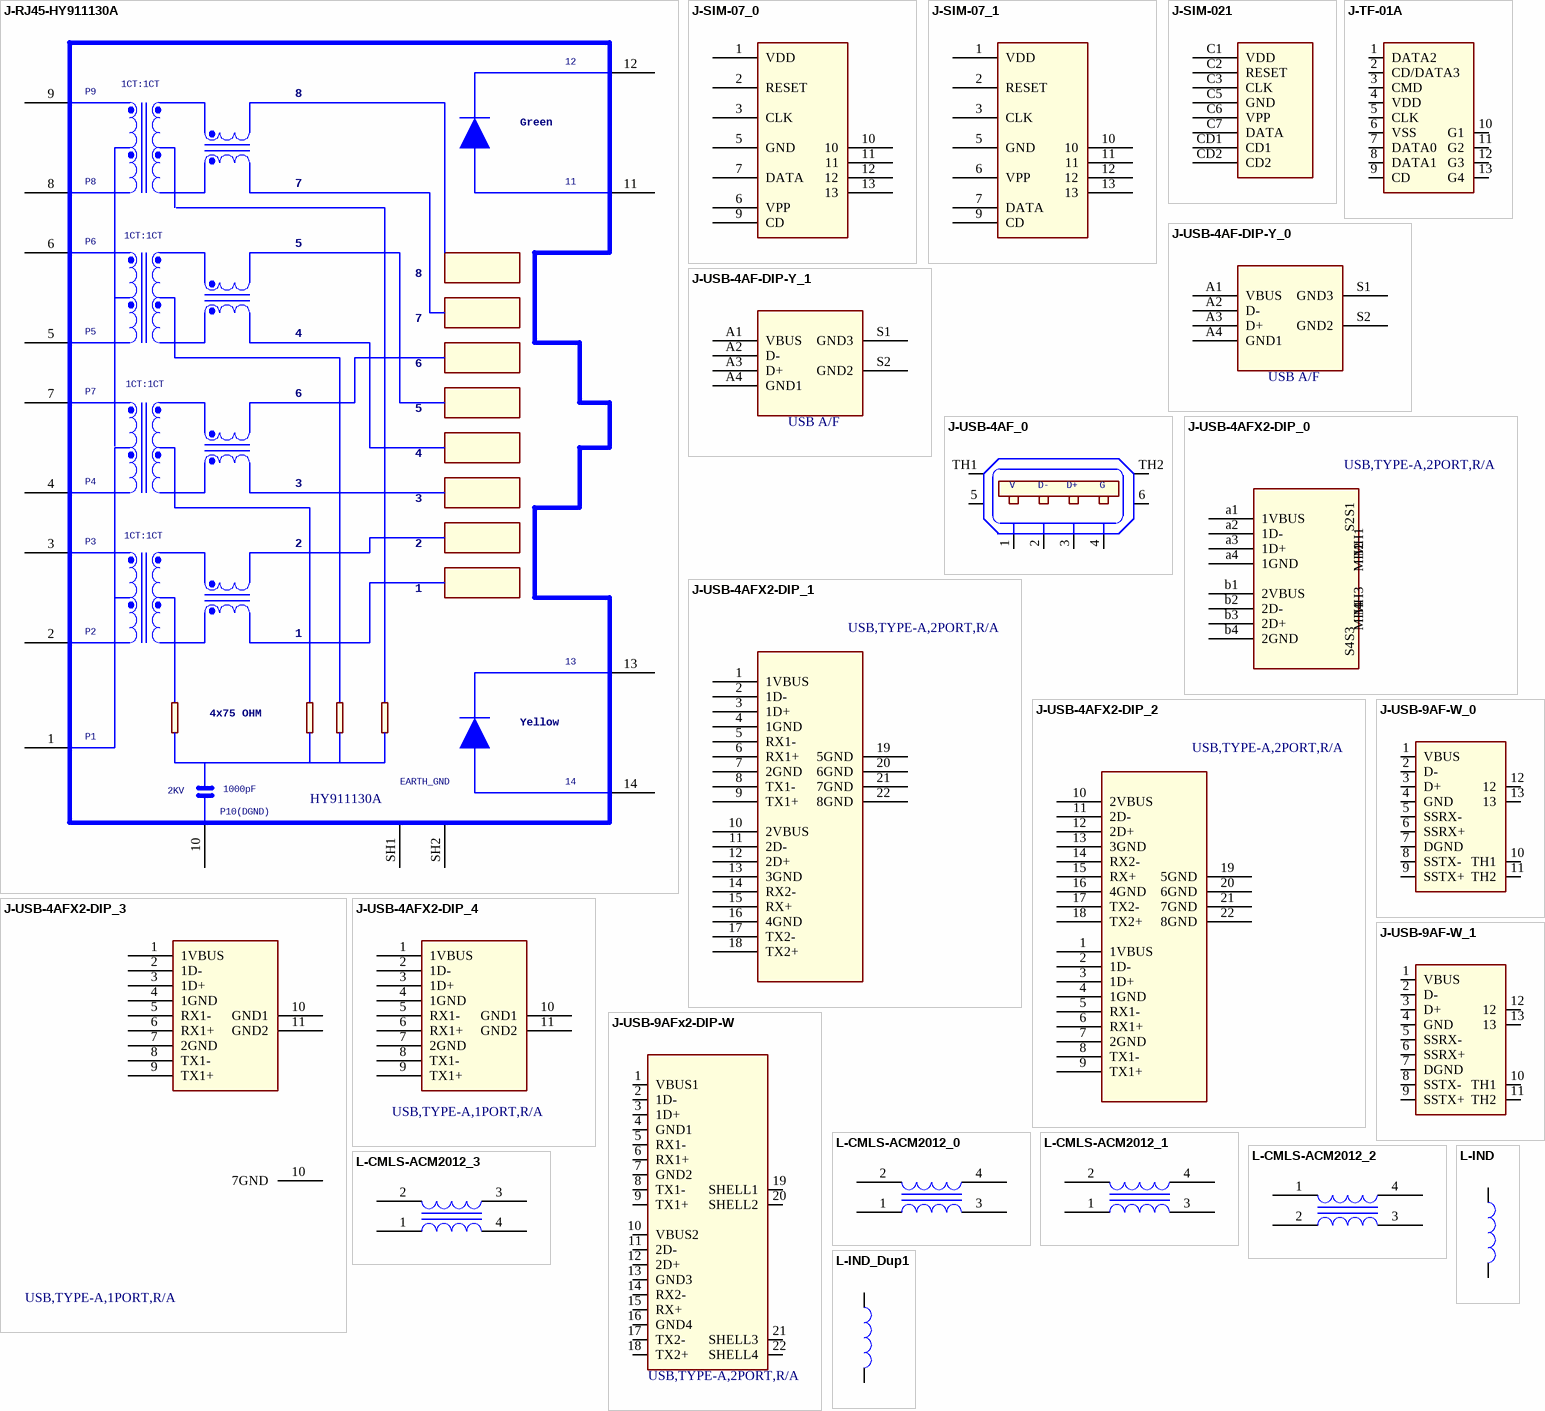
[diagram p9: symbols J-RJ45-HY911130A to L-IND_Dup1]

## J-RJ45-HY911130A
designator J?, comment HY911130A
Altium-Right: 360; Altium-Bottom: 520
pins: 1 CT1/2/3/4, 2 MDI_0+, 3 MDI_0-, 4 MDI_1+, 5 MDI_2+, 6 MDI_2-, 7 MDI_1-, 8 MDI_3+, 9 MDI_3-, 10 GND, 11 G_LED+, 12 G_LED-, 13 Y_LED-, 14 Y_LED+, SH1, SH2

## J-SIM-07_0
designator J?
Altium-Right: 60; Altium-Bottom: 130
pins: 1 VDD, 2 RESET, 3 CLK, 5 GND, 6 VPP, 7 DATA, 9 CD, 10, 11, 12, 13

## J-SIM-07_1
designator J?
Altium-Right: 60; Altium-Bottom: 130
pins: 1 VDD, 2 RESET, 3 CLK, 5 GND, 6 VPP, 7 DATA, 9 CD, 10, 11, 12, 13

## J-SIM-021
designator J?
Altium-Right: 50; Altium-Bottom: 90
pins: C1 VDD, C2 RESET, C3 CLK, C5 GND, C6 VPP, C7 DATA, CD1, CD2

## J-TF-01A
designator J?
Altium-Right: 60; Altium-Bottom: 100
pins: 1 DATA2, 2 CD/DATA3, 3 CMD, 4 VDD, 5 CLK, 6 VSS, 7 DATA0, 8 DATA1, 9 CD, 10 G1, 11 G2, 12 G3, 13 G4

## J-USB-4AF-DIP-Y_0
designator USB?, comment USB A/F
micro USB连接器; Altium-Right: 70
pins: A1 VBUS (power), A2 D-, A3 D+, A4 GND1 (power), S1 GND3, S2 GND2

## J-USB-4AF-DIP-Y_1
designator USB?, comment USB A/F
micro USB连接器; Altium-Right: 70
pins: A1 VBUS (power), A2 D-, A3 D+, A4 GND1 (power), S1 GND3, S2 GND2

## J-USB-4AF_0
designator J?
CLASS: IO; Altium-Right: 100; Altium-Bottom: 50
footprint USB_A_SMT
pins: 1 VCC, 2 DATA+, 3 DATA-, 4 GND, 5 SGND1, 6 SGND2, TH1, TH2

## J-USB-4AFX2-DIP_0
designator USB?, comment USB,TYPE-A,2PORT,R/A
USB,TYPE-A,2PORT,R/A,W/SHIELD; VSTNO: H00025; Altium-Right: 70; Altium-Bottom: 120
pins: a1 1VBUS, a2 1D-, a3 1D+, a4 1GND, b1 2VBUS, b2 2D-, b3 2D+, b4 2GND, S1 MH1, S2 MH2, S3 MH3, S4 MH4

## J-USB-4AFX2-DIP_1
designator USB?, comment USB,TYPE-A,2PORT,R/A
USB,TYPE-A,2PORT,R/A,W/SHIELD; VSTNO: H00025; Altium-Right: 70; Altium-Bottom: 220
pins: 1 1VBUS, 2 1D-, 3 1D+, 4 1GND, 5 RX1-, 6 RX1+, 7 2GND, 8 TX1-, 9 TX1+, 10 2VBUS, 11 2D-, 12 2D+, 13 3GND, 14 RX2-, 15 RX+, 16 4GND, 17 TX2-, 18 TX2+, 19 5GND, 20 6GND, 21 7GND, 22 8GND

## J-USB-4AFX2-DIP_2
designator USB?, comment USB,TYPE-A,2PORT,R/A
USB,TYPE-A,2PORT,R/A,W/SHIELD; VSTNO: H00025; Altium-Right: 70; Altium-Bottom: 220
pins: 1 1VBUS, 2 1D-, 3 1D+, 4 1GND, 5 RX1-, 6 RX1+, 7 2GND, 8 TX1-, 9 TX1+, 10 2VBUS, 11 2D-, 12 2D+, 13 3GND, 14 RX2-, 15 RX+, 16 4GND, 17 TX2-, 18 TX2+, 19 5GND, 20 6GND, 21 7GND, 22 8GND

## J-USB-4AFX2-DIP_3
designator USB?, comment USB,TYPE-A,1PORT,R/A
USB,TYPE-A,2PORT,R/A,W/SHIELD; VSTNO: H00025; Altium-Right: 70; Altium-Bottom: 100
pins: 1 1VBUS, 2 1D-, 3 1D+, 4 1GND, 5 RX1-, 6 RX1+, 7 2GND, 8 TX1-, 9 TX1+, 10 7GND, 10 GND1, 11 GND2

## J-USB-4AFX2-DIP_4
designator USB?, comment USB,TYPE-A,1PORT,R/A
USB,TYPE-A,2PORT,R/A,W/SHIELD; VSTNO: H00025; Altium-Right: 70; Altium-Bottom: 100
pins: 1 1VBUS, 2 1D-, 3 1D+, 4 1GND, 5 RX1-, 6 RX1+, 7 2GND, 8 TX1-, 9 TX1+, 10 GND1, 11 GND2

## J-USB-9AF-W_0
designator J?
USB,TYPE-A,2PORT,R/A,W/SHIELD; VSTNO: H00025; Altium-Right: 60; Altium-Bottom: 100
pins: 1 VBUS, 2 D-, 3 D+, 4 GND, 5 SSRX-, 6 SSRX+, 7 DGND, 8 SSTX-, 9 SSTX+, 10 TH1, 11 TH2, 12, 13

## J-USB-9AF-W_1
designator J?
USB,TYPE-A,2PORT,R/A,W/SHIELD; VSTNO: H00025; Altium-Right: 60; Altium-Bottom: 100
pins: 1 VBUS, 2 D-, 3 D+, 4 GND, 5 SSRX-, 6 SSRX+, 7 DGND, 8 SSTX-, 9 SSTX+, 10 TH1, 11 TH2, 12, 13

## J-USB-9AFx2-DIP-W
designator J?, comment USB,TYPE-A,2PORT,R/A
USB,TYPE-A,2PORT,R/A,W/SHIELD; VSTNO: H00025; Altium-Right: 80; Altium-Bottom: 210
pins: 1 VBUS1, 2 1D-, 3 1D+, 4 GND1, 5 RX1-, 6 RX1+, 7 GND2, 8 TX1-, 9 TX1+, 10 VBUS2, 11 2D-, 12 2D+, 13 GND3, 14 RX2-, 15 RX+, 16 GND4, 17 TX2-, 18 TX2+, 19 SHELL1, 20 SHELL2, 21 SHELL3, 22 SHELL4

## L-CMLS-ACM2012_0
designator CMLP?
Altium-Right: 40; Altium-Bottom: 20
pins: 1, 2, 3, 4

## L-CMLS-ACM2012_1
designator CMLP?
Altium-Right: 40; Altium-Bottom: 20
pins: 1, 2, 3, 4

## L-CMLS-ACM2012_2
designator CMLP?
Altium-Right: 40; Altium-Bottom: 20
pins: 1, 2, 3, 4

## L-CMLS-ACM2012_3
designator CMLP?
Altium-Right: 40; Altium-Bottom: 20
pins: 1, 2, 3, 4

## L-IND
designator L?
Altium-Right: 10; Altium-Bottom: 40
pins: 1, 2

## L-IND_Dup1
designator L?
Altium-Right: 10; Altium-Bottom: 40
pins: 1, 2

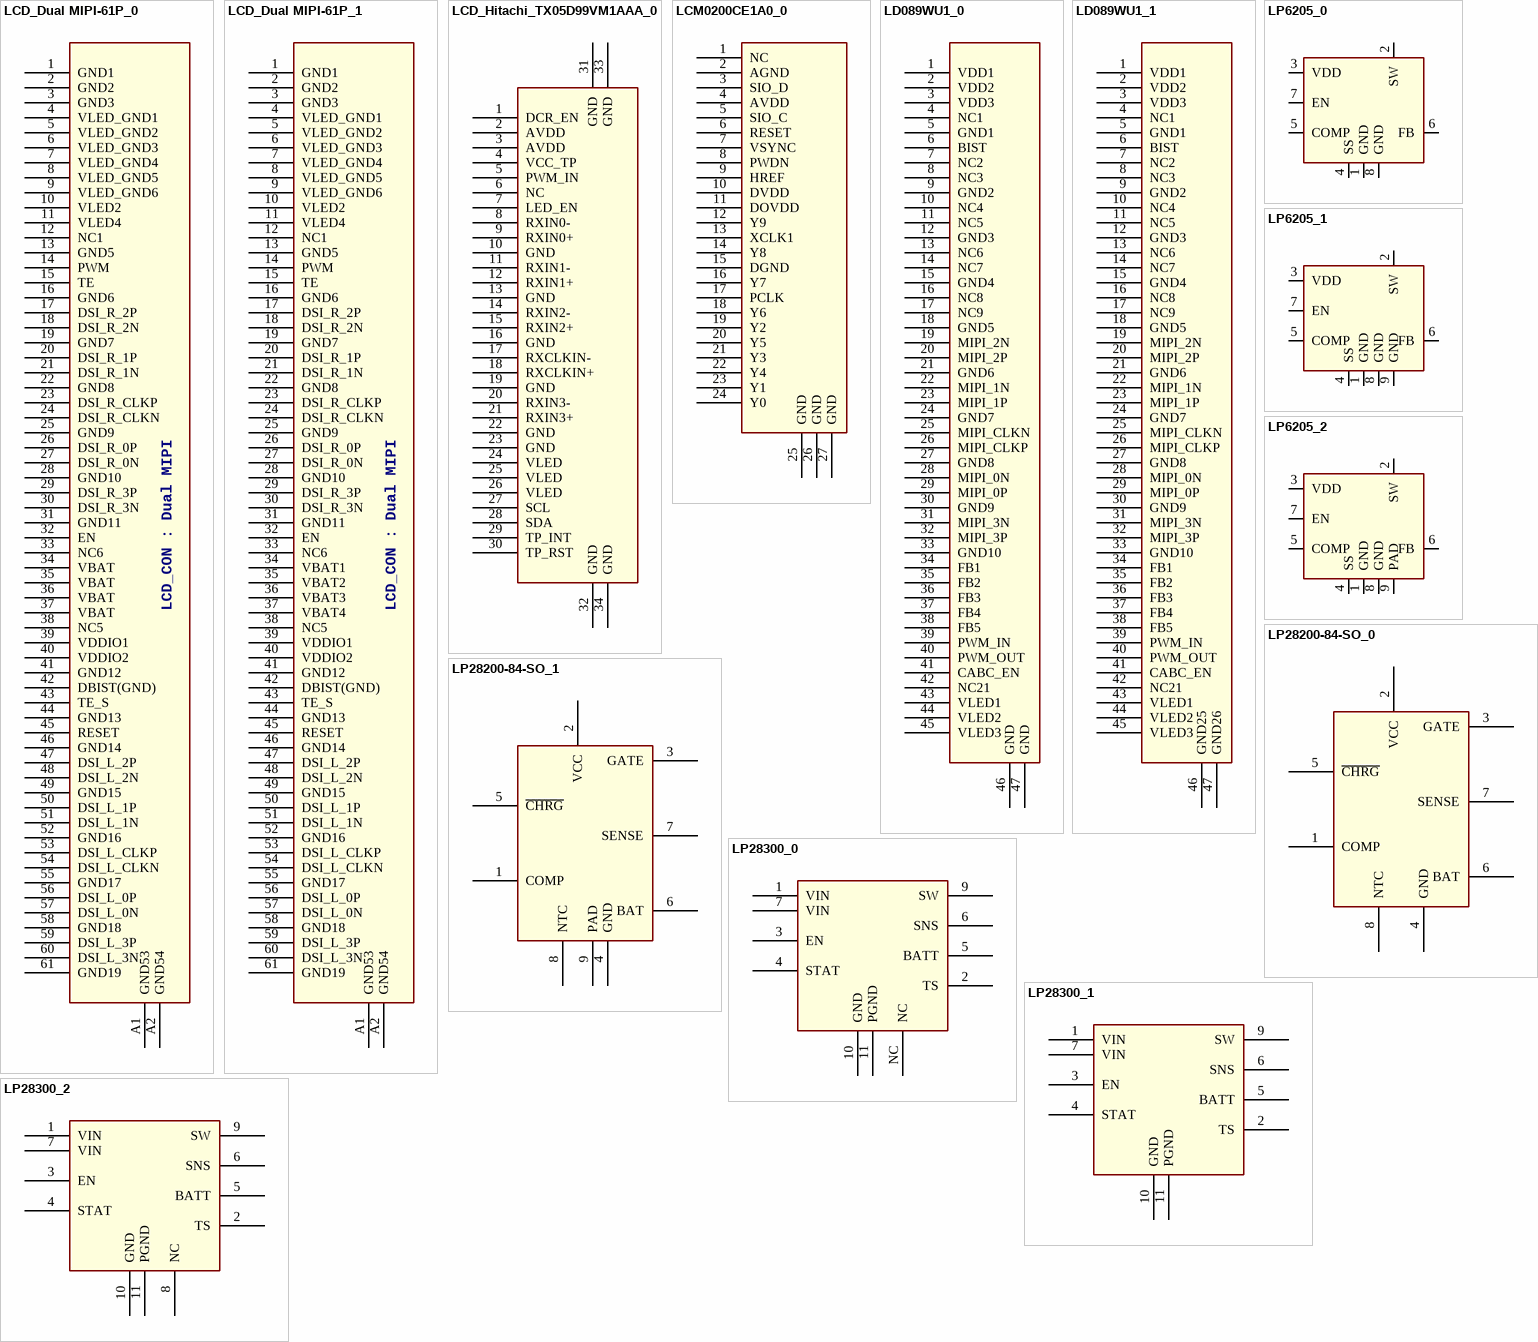
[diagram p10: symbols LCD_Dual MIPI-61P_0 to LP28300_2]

## LCD_Dual MIPI-61P_0
designator J?
Altium-Right: 80; Altium-Bottom: 640
pins: 1 GND1, 2 GND2, 3 GND3, 4 VLED_GND1, 5 VLED_GND2, 6 VLED_GND3, 7 VLED_GND4, 8 VLED_GND5, 9 VLED_GND6, 10 VLED2, 11 VLED4, 12 NC1, 13 GND5, 14 PWM, 15 TE, 16 GND6, 17 DSI_R_2P, 18 DSI_R_2N, 19 GND7, 20 DSI_R_1P, 21 DSI_R_1N, 22 GND8, 23 DSI_R_CLKP, 24 DSI_R_CLKN, 25 GND9, 26 DSI_R_0P, 27 DSI_R_0N, 28 GND10, 29 DSI_R_3P, 30 DSI_R_3N, 31 GND11, 32 EN, 33 NC6, 34 VBAT, 35 VBAT, 36 VBAT, 37 VBAT, 38 NC5, 39 VDDIO1, 40 VDDIO2, 41 GND12, 42 DBIST(GND), 43 TE_S, 44 GND13, 45 RESET, 46 GND14, 47 DSI_L_2P, 48 DSI_L_2N, 49 GND15, 50 DSI_L_1P, 51 DSI_L_1N, 52 GND16, 53 DSI_L_CLKP, 54 DSI_L_CLKN, 55 GND17, 56 DSI_L_0P, 57 DSI_L_0N, 58 GND18, 59 DSI_L_3P, 60 DSI_L_3N, 61 GND19, A1 GND53, A2 GND54

## LCD_Dual MIPI-61P_1
designator J?
Altium-Right: 80; Altium-Bottom: 640
pins: 1 GND1, 2 GND2, 3 GND3, 4 VLED_GND1, 5 VLED_GND2, 6 VLED_GND3, 7 VLED_GND4, 8 VLED_GND5, 9 VLED_GND6, 10 VLED2, 11 VLED4, 12 NC1, 13 GND5, 14 PWM, 15 TE, 16 GND6, 17 DSI_R_2P, 18 DSI_R_2N, 19 GND7, 20 DSI_R_1P, 21 DSI_R_1N, 22 GND8, 23 DSI_R_CLKP, 24 DSI_R_CLKN, 25 GND9, 26 DSI_R_0P, 27 DSI_R_0N, 28 GND10, 29 DSI_R_3P, 30 DSI_R_3N, 31 GND11, 32 EN, 33 NC6, 34 VBAT1, 35 VBAT2, 36 VBAT3, 37 VBAT4, 38 NC5, 39 VDDIO1, 40 VDDIO2, 41 GND12, 42 DBIST(GND), 43 TE_S, 44 GND13, 45 RESET, 46 GND14, 47 DSI_L_2P, 48 DSI_L_2N, 49 GND15, 50 DSI_L_1P, 51 DSI_L_1N, 52 GND16, 53 DSI_L_CLKP, 54 DSI_L_CLKN, 55 GND17, 56 DSI_L_0P, 57 DSI_L_0N, 58 GND18, 59 DSI_L_3P, 60 DSI_L_3N, 61 GND19, A1 GND53, A2 GND54

## LCD_Hitachi_TX05D99VM1AAA_0
designator CON?
Altium-Right: 80; Altium-Bottom: 330
pins: 1 DCR_EN, 2 AVDD (power), 3 AVDD (power), 4 VCC_TP, 5 PWM_IN, 6 NC, 7 LED_EN, 8 RXIN0-, 9 RXIN0+, 10 GND (power), 11 RXIN1-, 12 RXIN1+, 13 GND (power), 14 RXIN2-, 15 RXIN2+, 16 GND (power), 17 RXCLKIN-, 18 RXCLKIN+, 19 GND (power), 20 RXIN3-, 21 RXIN3+, 22 GND (power), 23 GND (power), 24 VLED (power), 25 VLED (power), 26 VLED (power), 27 SCL, 28 SDA, 29 TP_INT, 30 TP_RST, 31 GND (power), 32 GND (power), 33 GND (power), 34 GND (power)

## LCM0200CE1A0_0
designator U?
Altium-Right: 70; Altium-Bottom: 260
pins: 1 NC, 2 AGND, 3 SIO_D, 4 AVDD, 5 SIO_C, 6 RESET, 7 VSYNC, 8 PWDN, 9 HREF, 10 DVDD, 11 DOVDD, 12 Y9, 13 XCLK1, 14 Y8, 15 DGND, 16 Y7, 17 PCLK, 18 Y6, 19 Y2, 20 Y5, 21 Y3, 22 Y4, 23 Y1, 24 Y0, 25 GND, 26 GND, 27 GND

## LD089WU1_0
designator U?
Altium-Right: 60; Altium-Bottom: 480
pins: 1 VDD1, 2 VDD2, 3 VDD3, 4 NC1, 5 GND1, 6 BIST, 7 NC2, 8 NC3, 9 GND2, 10 NC4, 11 NC5, 12 GND3, 13 NC6, 14 NC7, 15 GND4, 16 NC8, 17 NC9, 18 GND5, 19 MIPI_2N, 20 MIPI_2P, 21 GND6, 22 MIPI_1N, 23 MIPI_1P, 24 GND7, 25 MIPI_CLKN, 26 MIPI_CLKP, 27 GND8, 28 MIPI_0N, 29 MIPI_0P, 30 GND9, 31 MIPI_3N, 32 MIPI_3P, 33 GND10, 34 FB1, 35 FB2, 36 FB3, 37 FB4, 38 FB5, 39 PWM_IN, 40 PWM_OUT, 41 CABC_EN, 42 NC21, 43 VLED1, 44 VLED2, 45 VLED3, 46 GND, 47 GND

## LD089WU1_1
designator U?
Altium-Right: 60; Altium-Bottom: 480
pins: 1 VDD1, 2 VDD2, 3 VDD3, 4 NC1, 5 GND1, 6 BIST, 7 NC2, 8 NC3, 9 GND2, 10 NC4, 11 NC5, 12 GND3, 13 NC6, 14 NC7, 15 GND4, 16 NC8, 17 NC9, 18 GND5, 19 MIPI_2N, 20 MIPI_2P, 21 GND6, 22 MIPI_1N, 23 MIPI_1P, 24 GND7, 25 MIPI_CLKN, 26 MIPI_CLKP, 27 GND8, 28 MIPI_0N, 29 MIPI_0P, 30 GND9, 31 MIPI_3N, 32 MIPI_3P, 33 GND10, 34 FB1, 35 FB2, 36 FB3, 37 FB4, 38 FB5, 39 PWM_IN, 40 PWM_OUT, 41 CABC_EN, 42 NC21, 43 VLED1, 44 VLED2, 45 VLED3, 46 GND25, 47 GND26

## LP6205_0
designator U?
Altium-Right: 80; Altium-Bottom: 70
pins: 1 GND, 2 SW, 3 VDD, 4 SS, 5 COMP, 6 FB, 7 EN, 8 GND

## LP6205_1
designator U?
Altium-Right: 80; Altium-Bottom: 70
pins: 1 GND, 2 SW, 3 VDD, 4 SS, 5 COMP, 6 FB, 7 EN, 8 GND, 9 GND

## LP6205_2
designator U?
Altium-Right: 80; Altium-Bottom: 70
pins: 1 GND, 2 SW, 3 VDD, 4 SS, 5 COMP, 6 FB, 7 EN, 8 GND, 9 PAD

## LP28200-84-SO_0
designator U?
Altium-Right: 90; Altium-Bottom: 130
footprint SOP8
pins: 1 COMP, 2 VCC, 3 GATE, 4 GND, 5 ~{CHRG}, 6 BAT, 7 SENSE, 8 NTC

## LP28200-84-SO_1
designator U?
Altium-Right: 90; Altium-Bottom: 130
footprint SOP8
pins: 1 COMP, 2 VCC, 3 GATE, 4 GND, 5 ~{CHRG}, 6 BAT, 7 SENSE, 8 NTC, 9 PAD

## LP28300_0
designator U?
Altium-Right: 100
footprint TDFN10
pins: 1 VIN, 2 TS, 3 EN, 4 STAT, 5 BATT, 6 SNS, 7 VIN, 9 SW, 10 GND, 11 PGND, NC

## LP28300_1
designator U?
Altium-Right: 100
footprint TDFN10
pins: 1 VIN, 2 TS, 3 EN, 4 STAT, 5 BATT, 6 SNS, 7 VIN, 9 SW, 10 GND, 11 PGND

## LP28300_2
designator U?
Altium-Right: 100
footprint TDFN10
pins: 1 VIN, 2 TS, 3 EN, 4 STAT, 5 BATT, 6 SNS, 7 VIN, 8 NC, 9 SW, 10 GND, 11 PGND

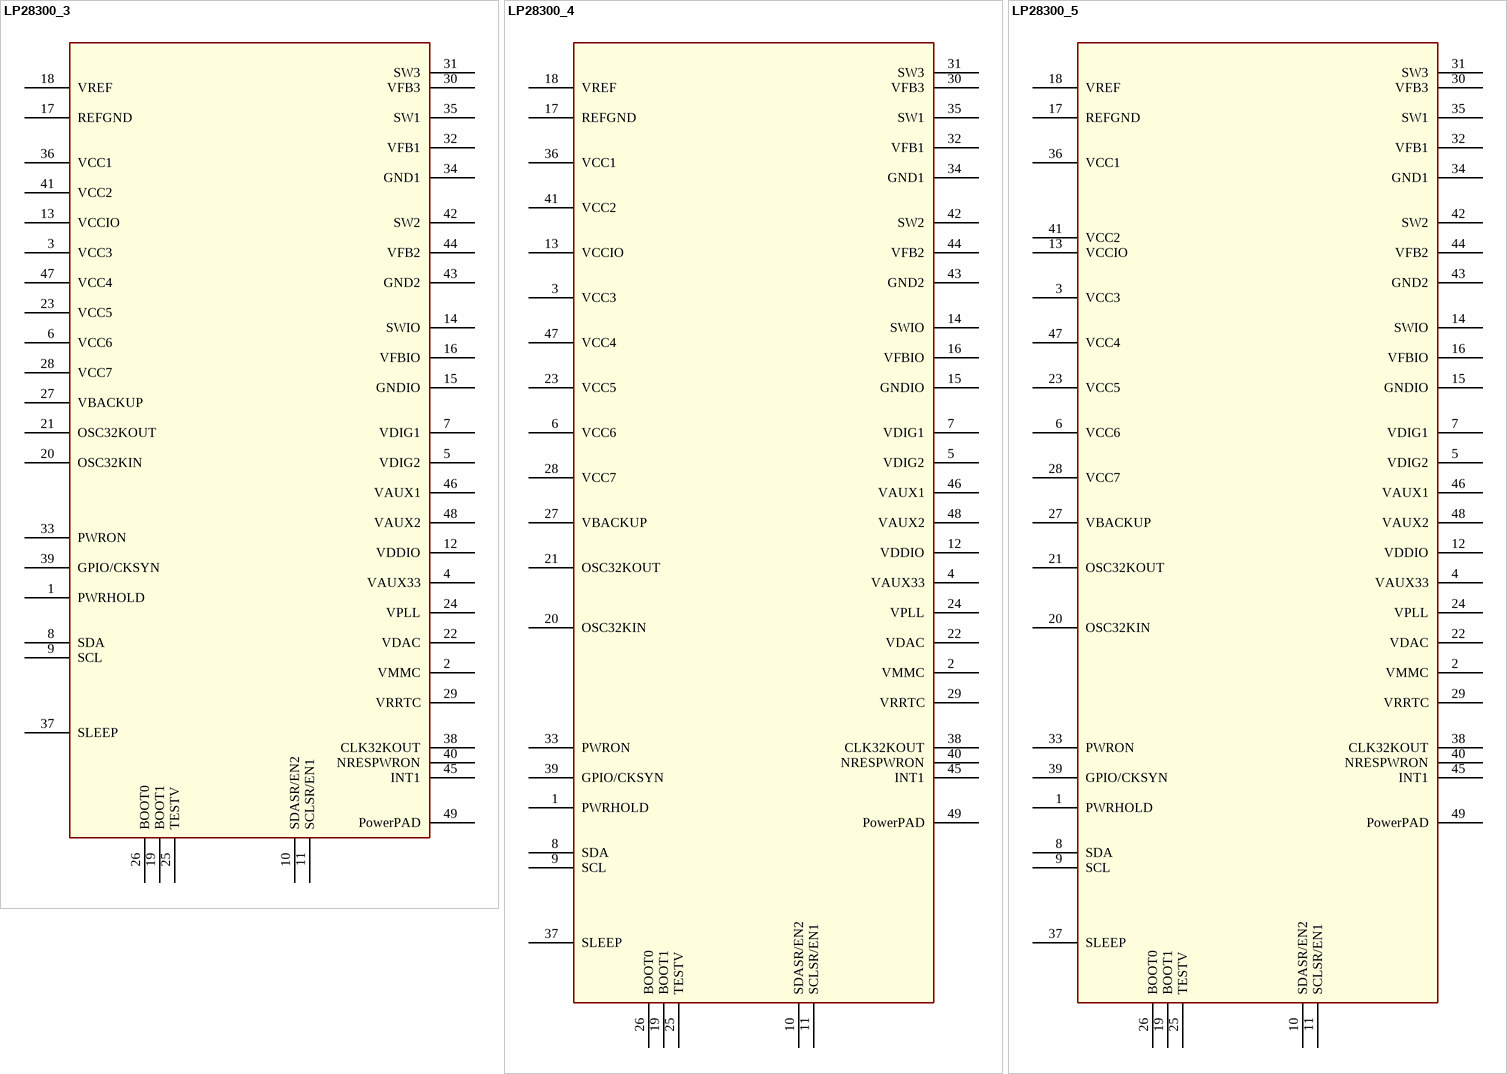
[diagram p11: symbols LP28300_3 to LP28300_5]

## LP28300_3
designator U?
Altium-Right: 240; Altium-Bottom: 530
footprint TDFN10
pins: 1 PWRHOLD, 2 VMMC, 3 VCC3, 4 VAUX33, 5 VDIG2, 6 VCC6, 7 VDIG1, 8 SDA, 9 SCL, 10 SDASR/EN2, 11 SCLSR/EN1, 12 VDDIO, 13 VCCIO, 14 SWIO, 15 GNDIO, 16 VFBIO, 17 REFGND, 18 VREF, 19 BOOT1, 20 OSC32KIN, 21 OSC32KOUT, 22 VDAC, 23 VCC5, 24 VPLL, 25 TESTV, 26 BOOT0, 27 VBACKUP, 28 VCC7, 29 VRRTC, 30 VFB3, 31 SW3, 32 VFB1, 33 PWRON, 34 GND1, 35 SW1, 36 VCC1, 37 SLEEP, 38 CLK32KOUT, 39 GPIO/CKSYN, 40 NRESPWRON, 41 VCC2, 42 SW2, 43 GND2, 44 VFB2, 45 INT1, 46 VAUX1, 47 VCC4, 48 VAUX2, 49 PowerPAD

## LP28300_4
designator U?
Altium-Right: 240; Altium-Bottom: 640
footprint TDFN10
pins: 1 PWRHOLD, 2 VMMC, 3 VCC3, 4 VAUX33, 5 VDIG2, 6 VCC6, 7 VDIG1, 8 SDA, 9 SCL, 10 SDASR/EN2, 11 SCLSR/EN1, 12 VDDIO, 13 VCCIO, 14 SWIO, 15 GNDIO, 16 VFBIO, 17 REFGND, 18 VREF, 19 BOOT1, 20 OSC32KIN, 21 OSC32KOUT, 22 VDAC, 23 VCC5, 24 VPLL, 25 TESTV, 26 BOOT0, 27 VBACKUP, 28 VCC7, 29 VRRTC, 30 VFB3, 31 SW3, 32 VFB1, 33 PWRON, 34 GND1, 35 SW1, 36 VCC1, 37 SLEEP, 38 CLK32KOUT, 39 GPIO/CKSYN, 40 NRESPWRON, 41 VCC2, 42 SW2, 43 GND2, 44 VFB2, 45 INT1, 46 VAUX1, 47 VCC4, 48 VAUX2, 49 PowerPAD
